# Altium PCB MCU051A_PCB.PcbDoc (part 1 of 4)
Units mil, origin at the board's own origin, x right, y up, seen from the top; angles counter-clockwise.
Board outline 4000 x 6000 mil, 6 copper layers (Top Layer, Signal Layer 1, Signal Layer 2, Signal Layer 3, Signal Layer 4, Bottom Layer), stack 60.4 mil thick; 193 components, 239 nets, 864 pads, 621 vias.
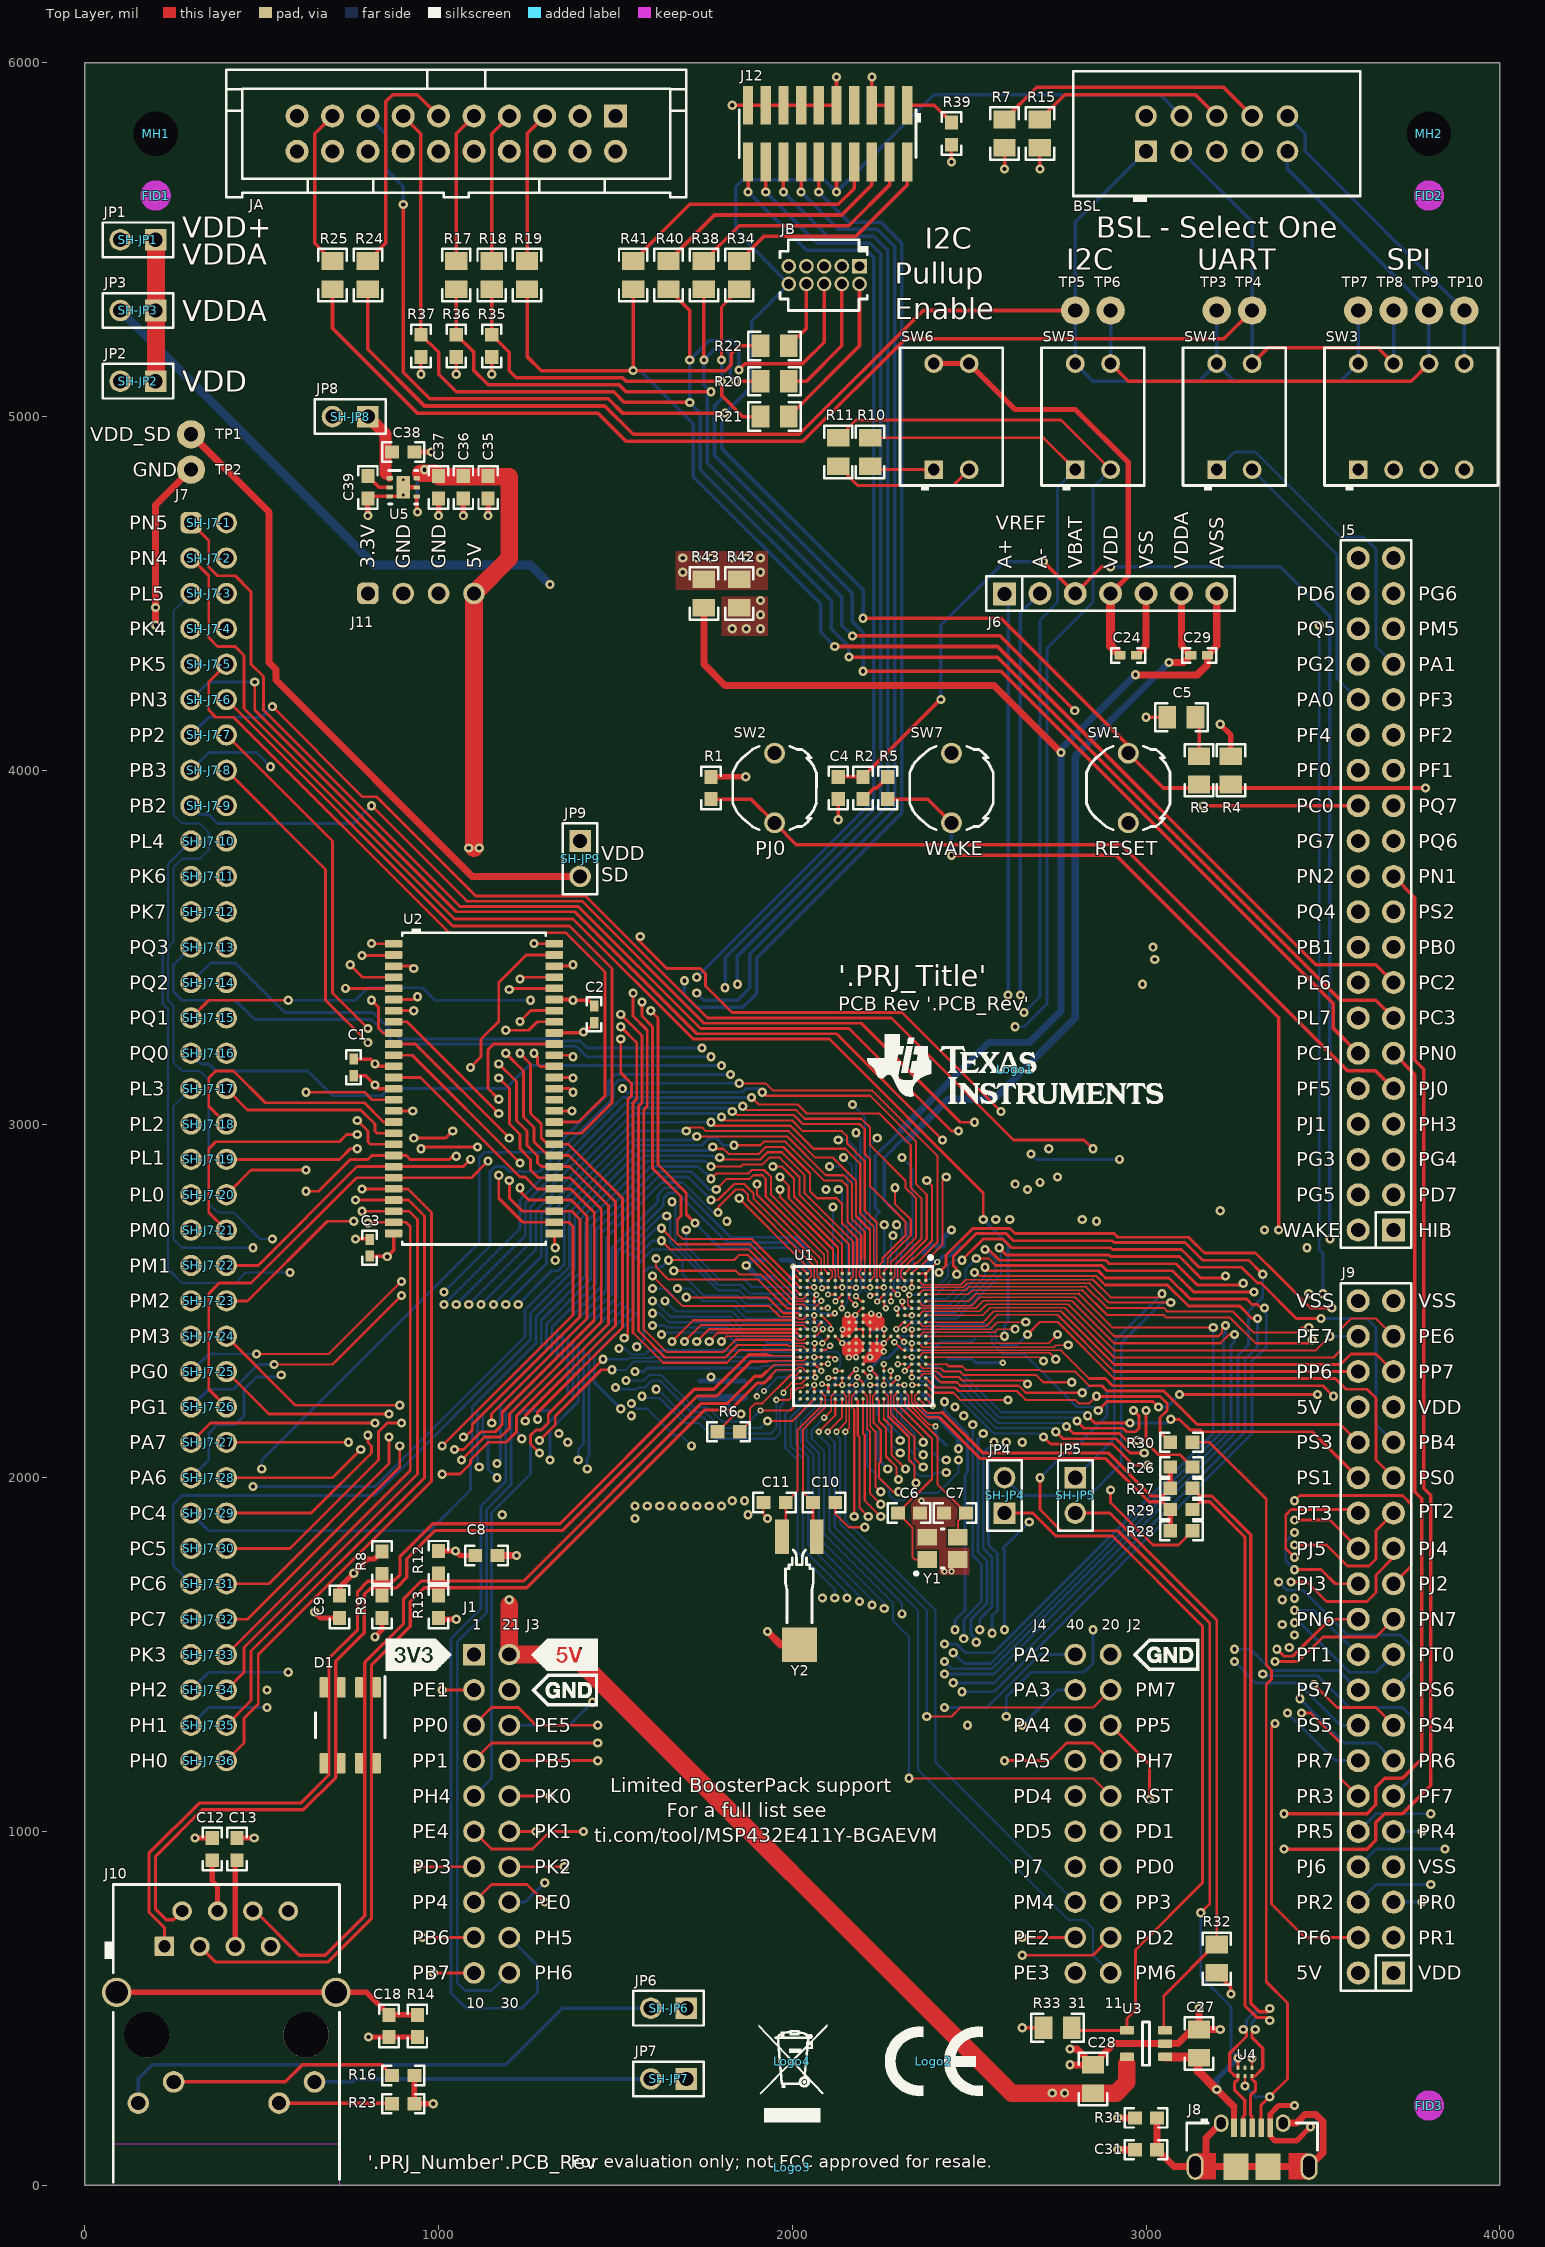
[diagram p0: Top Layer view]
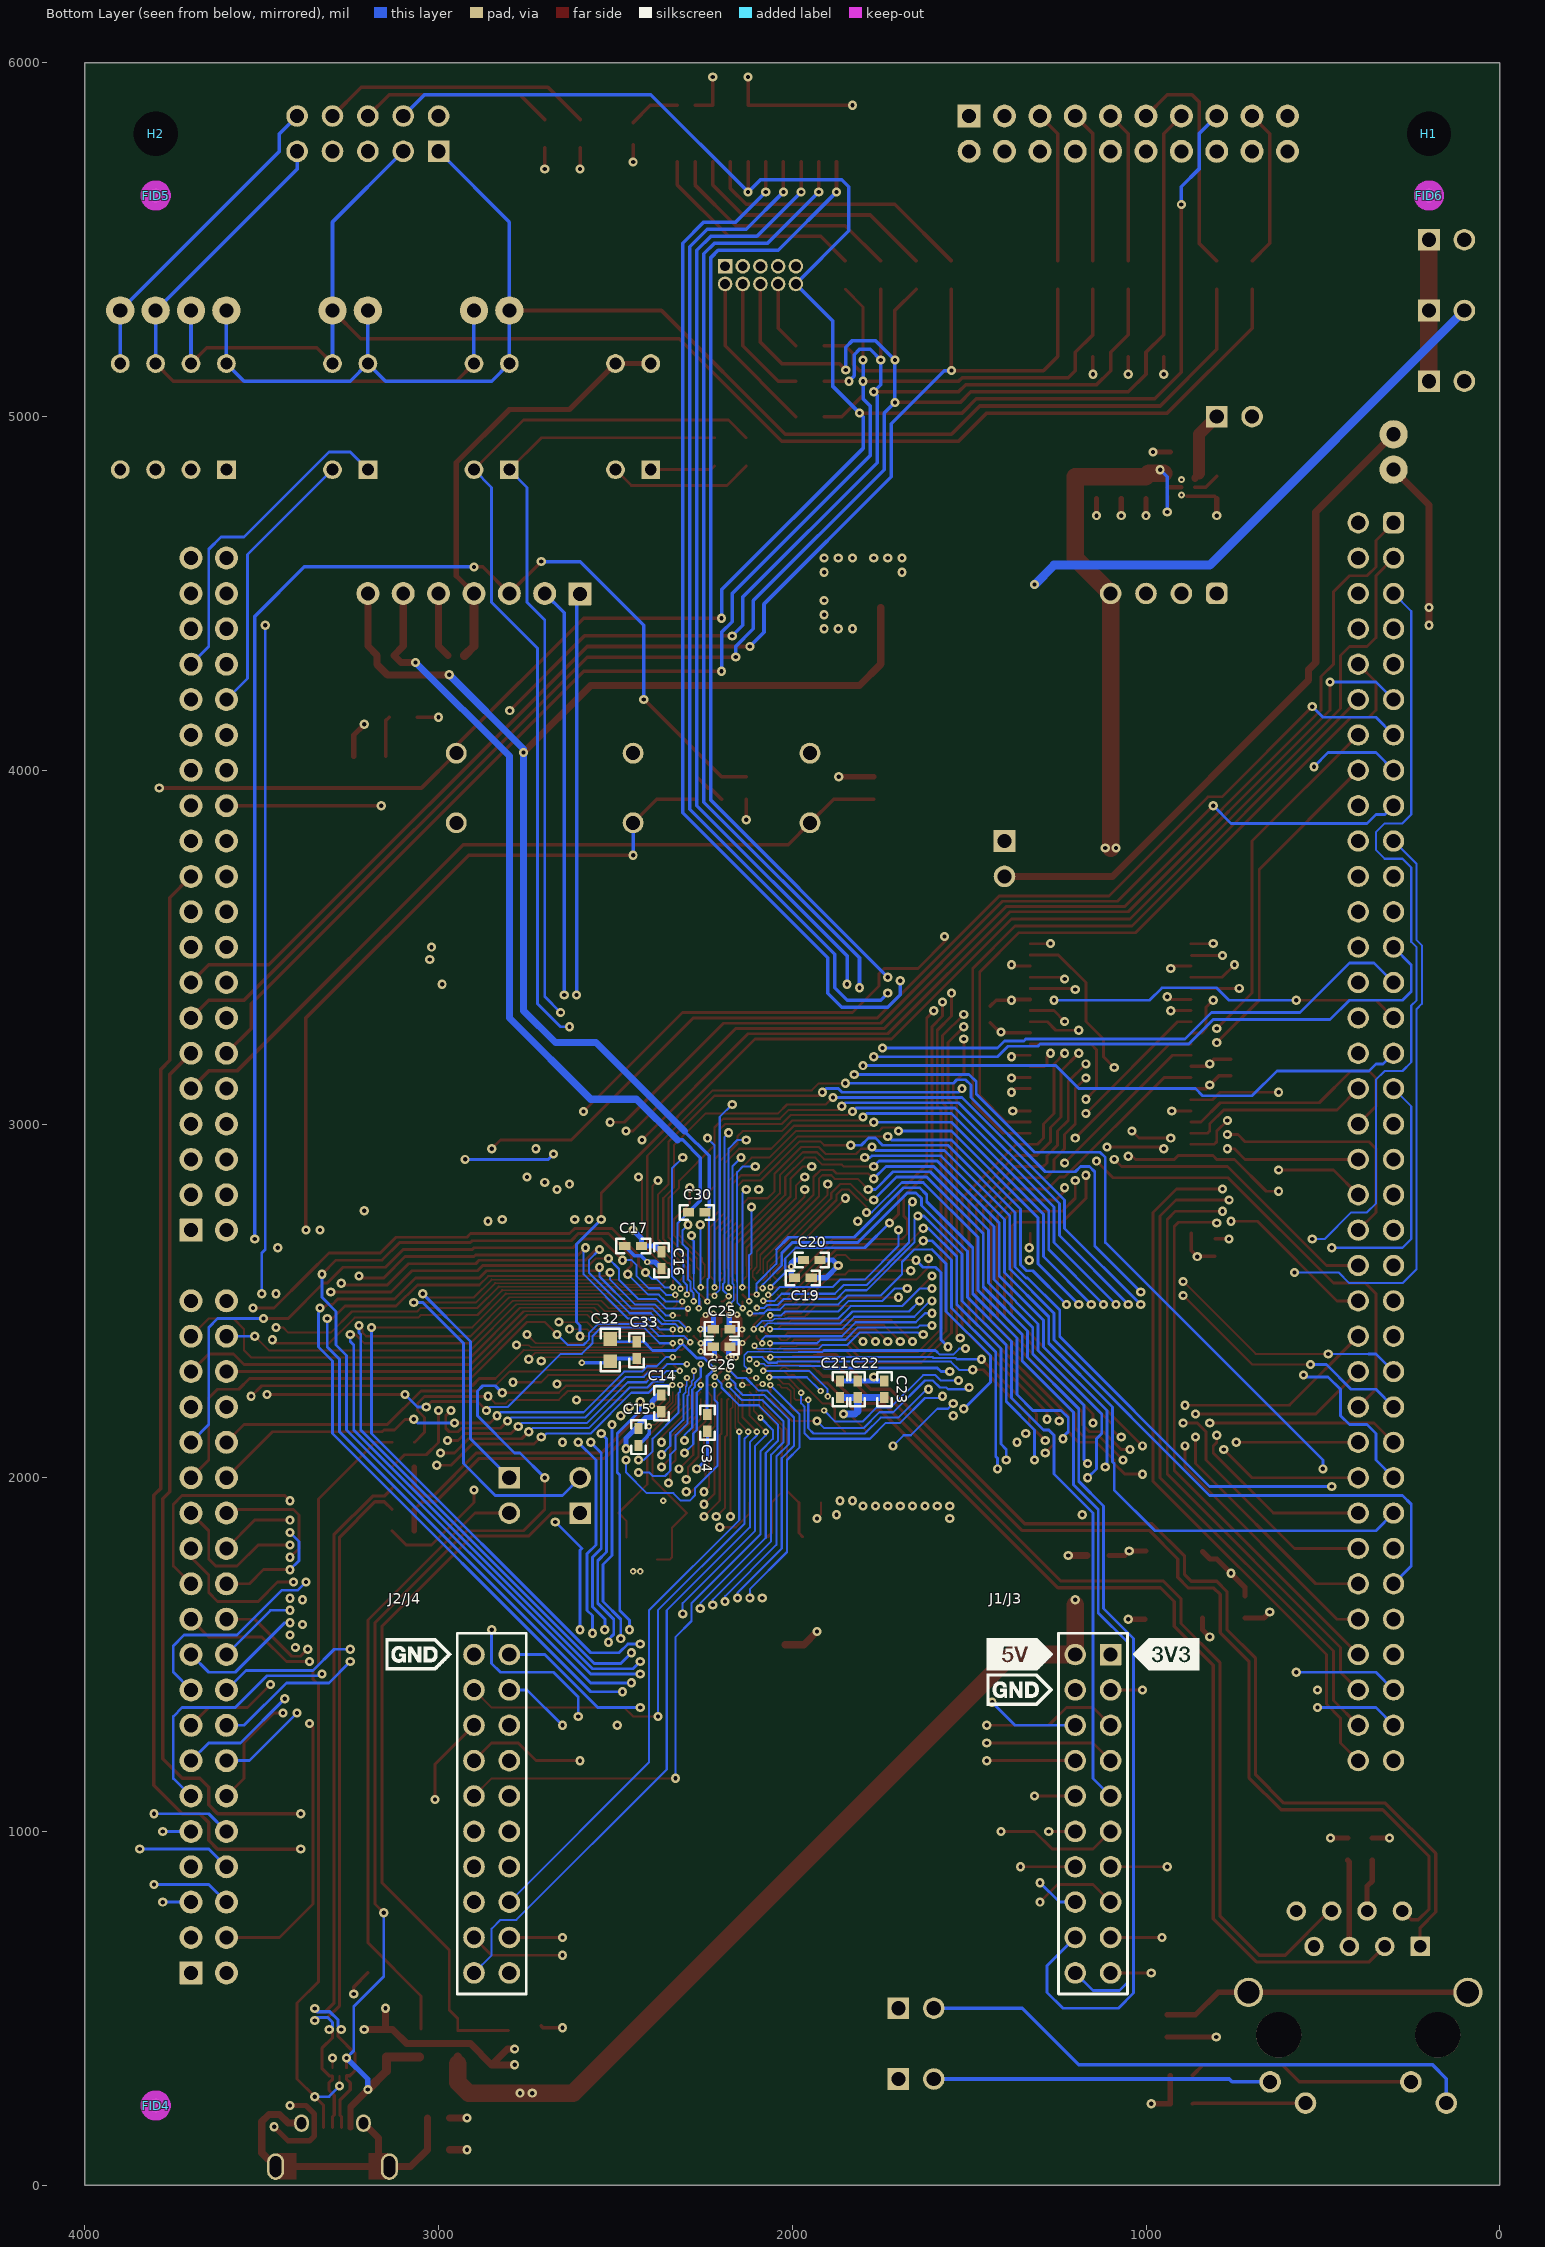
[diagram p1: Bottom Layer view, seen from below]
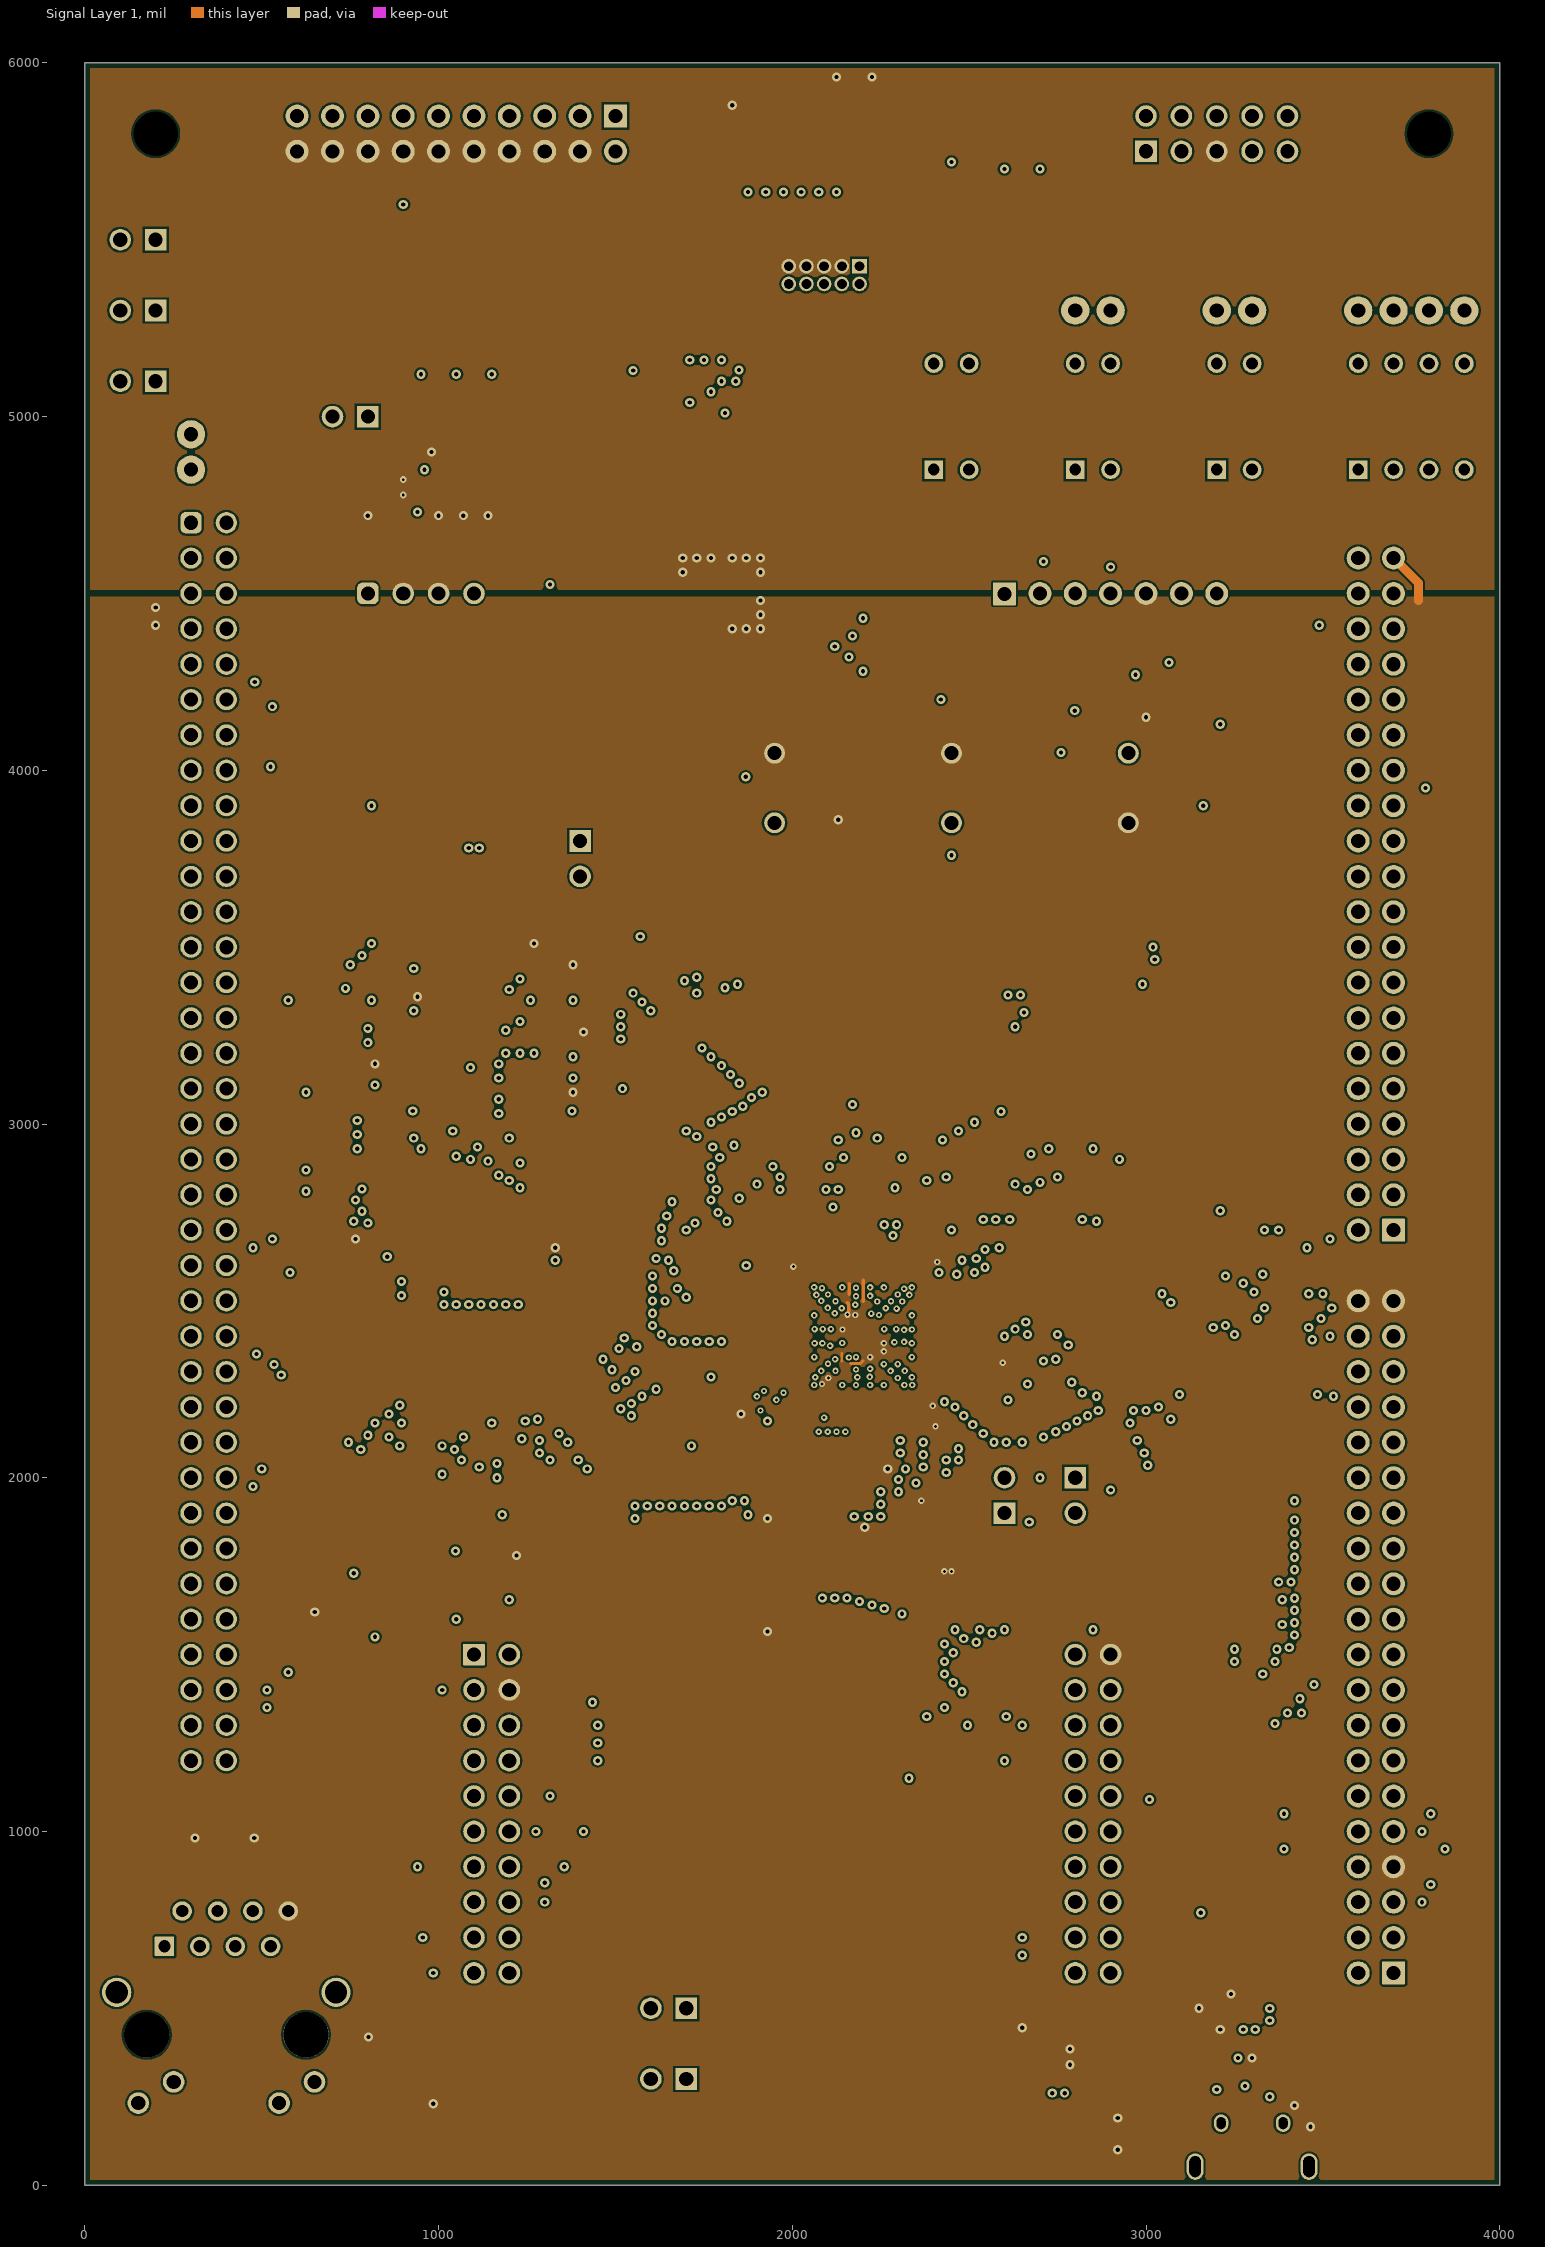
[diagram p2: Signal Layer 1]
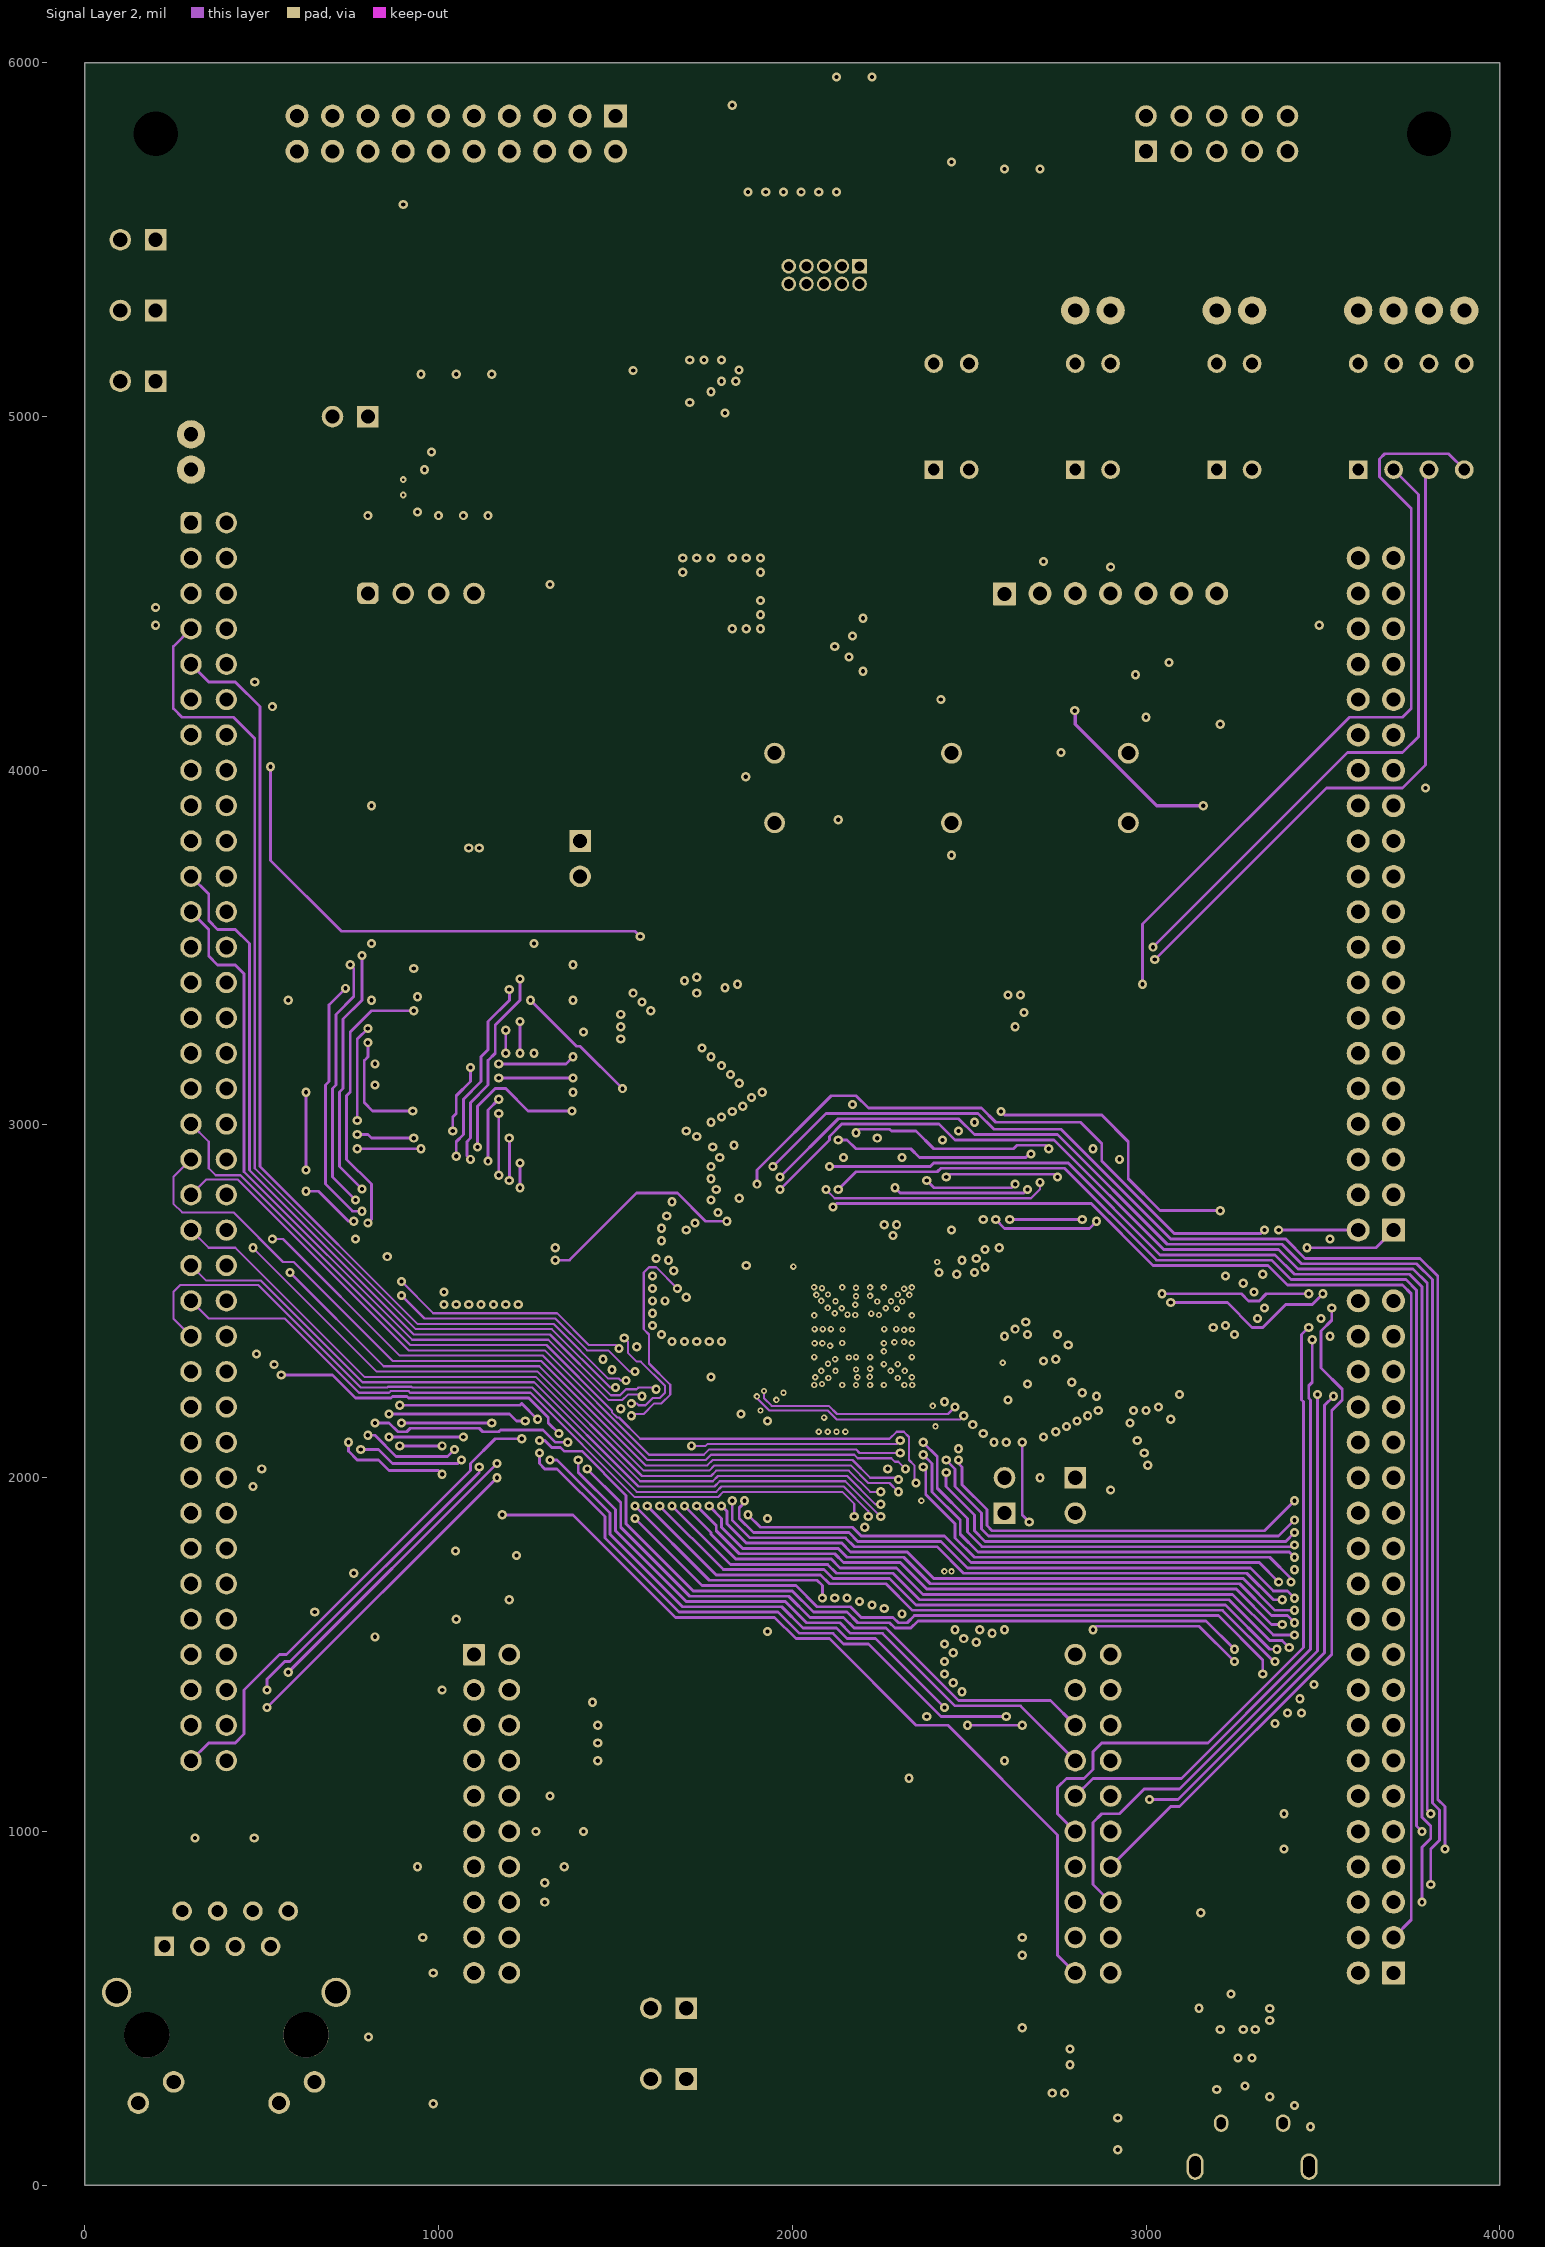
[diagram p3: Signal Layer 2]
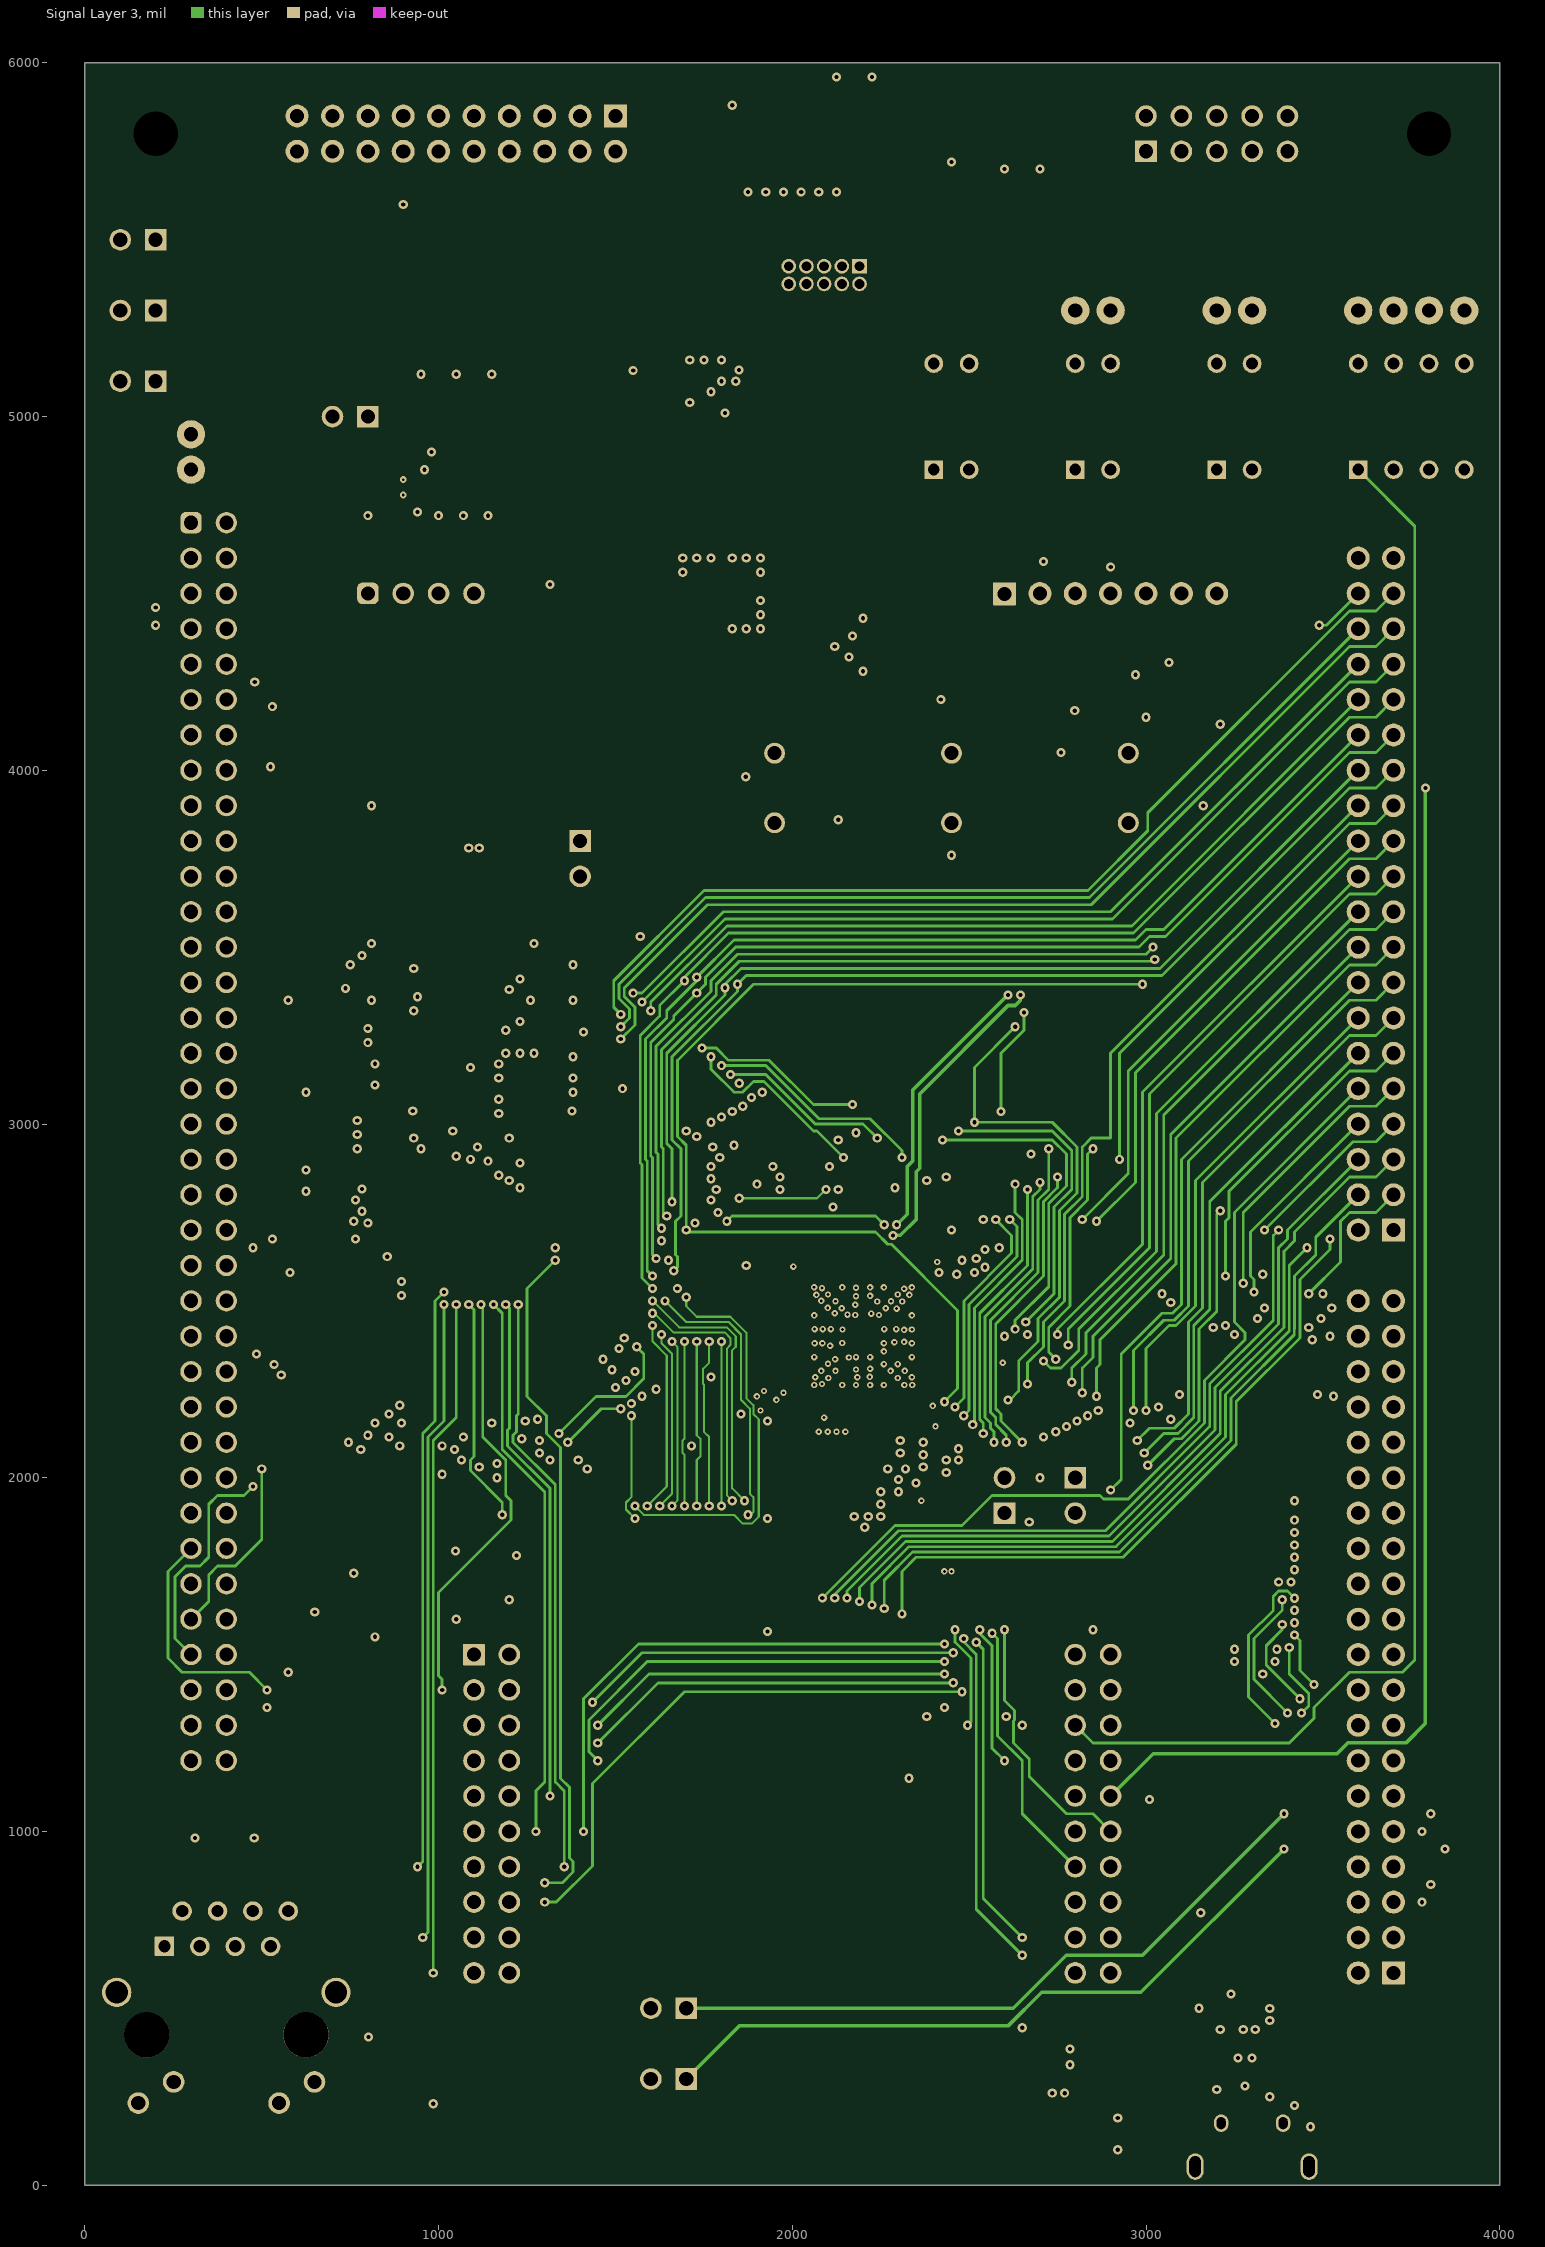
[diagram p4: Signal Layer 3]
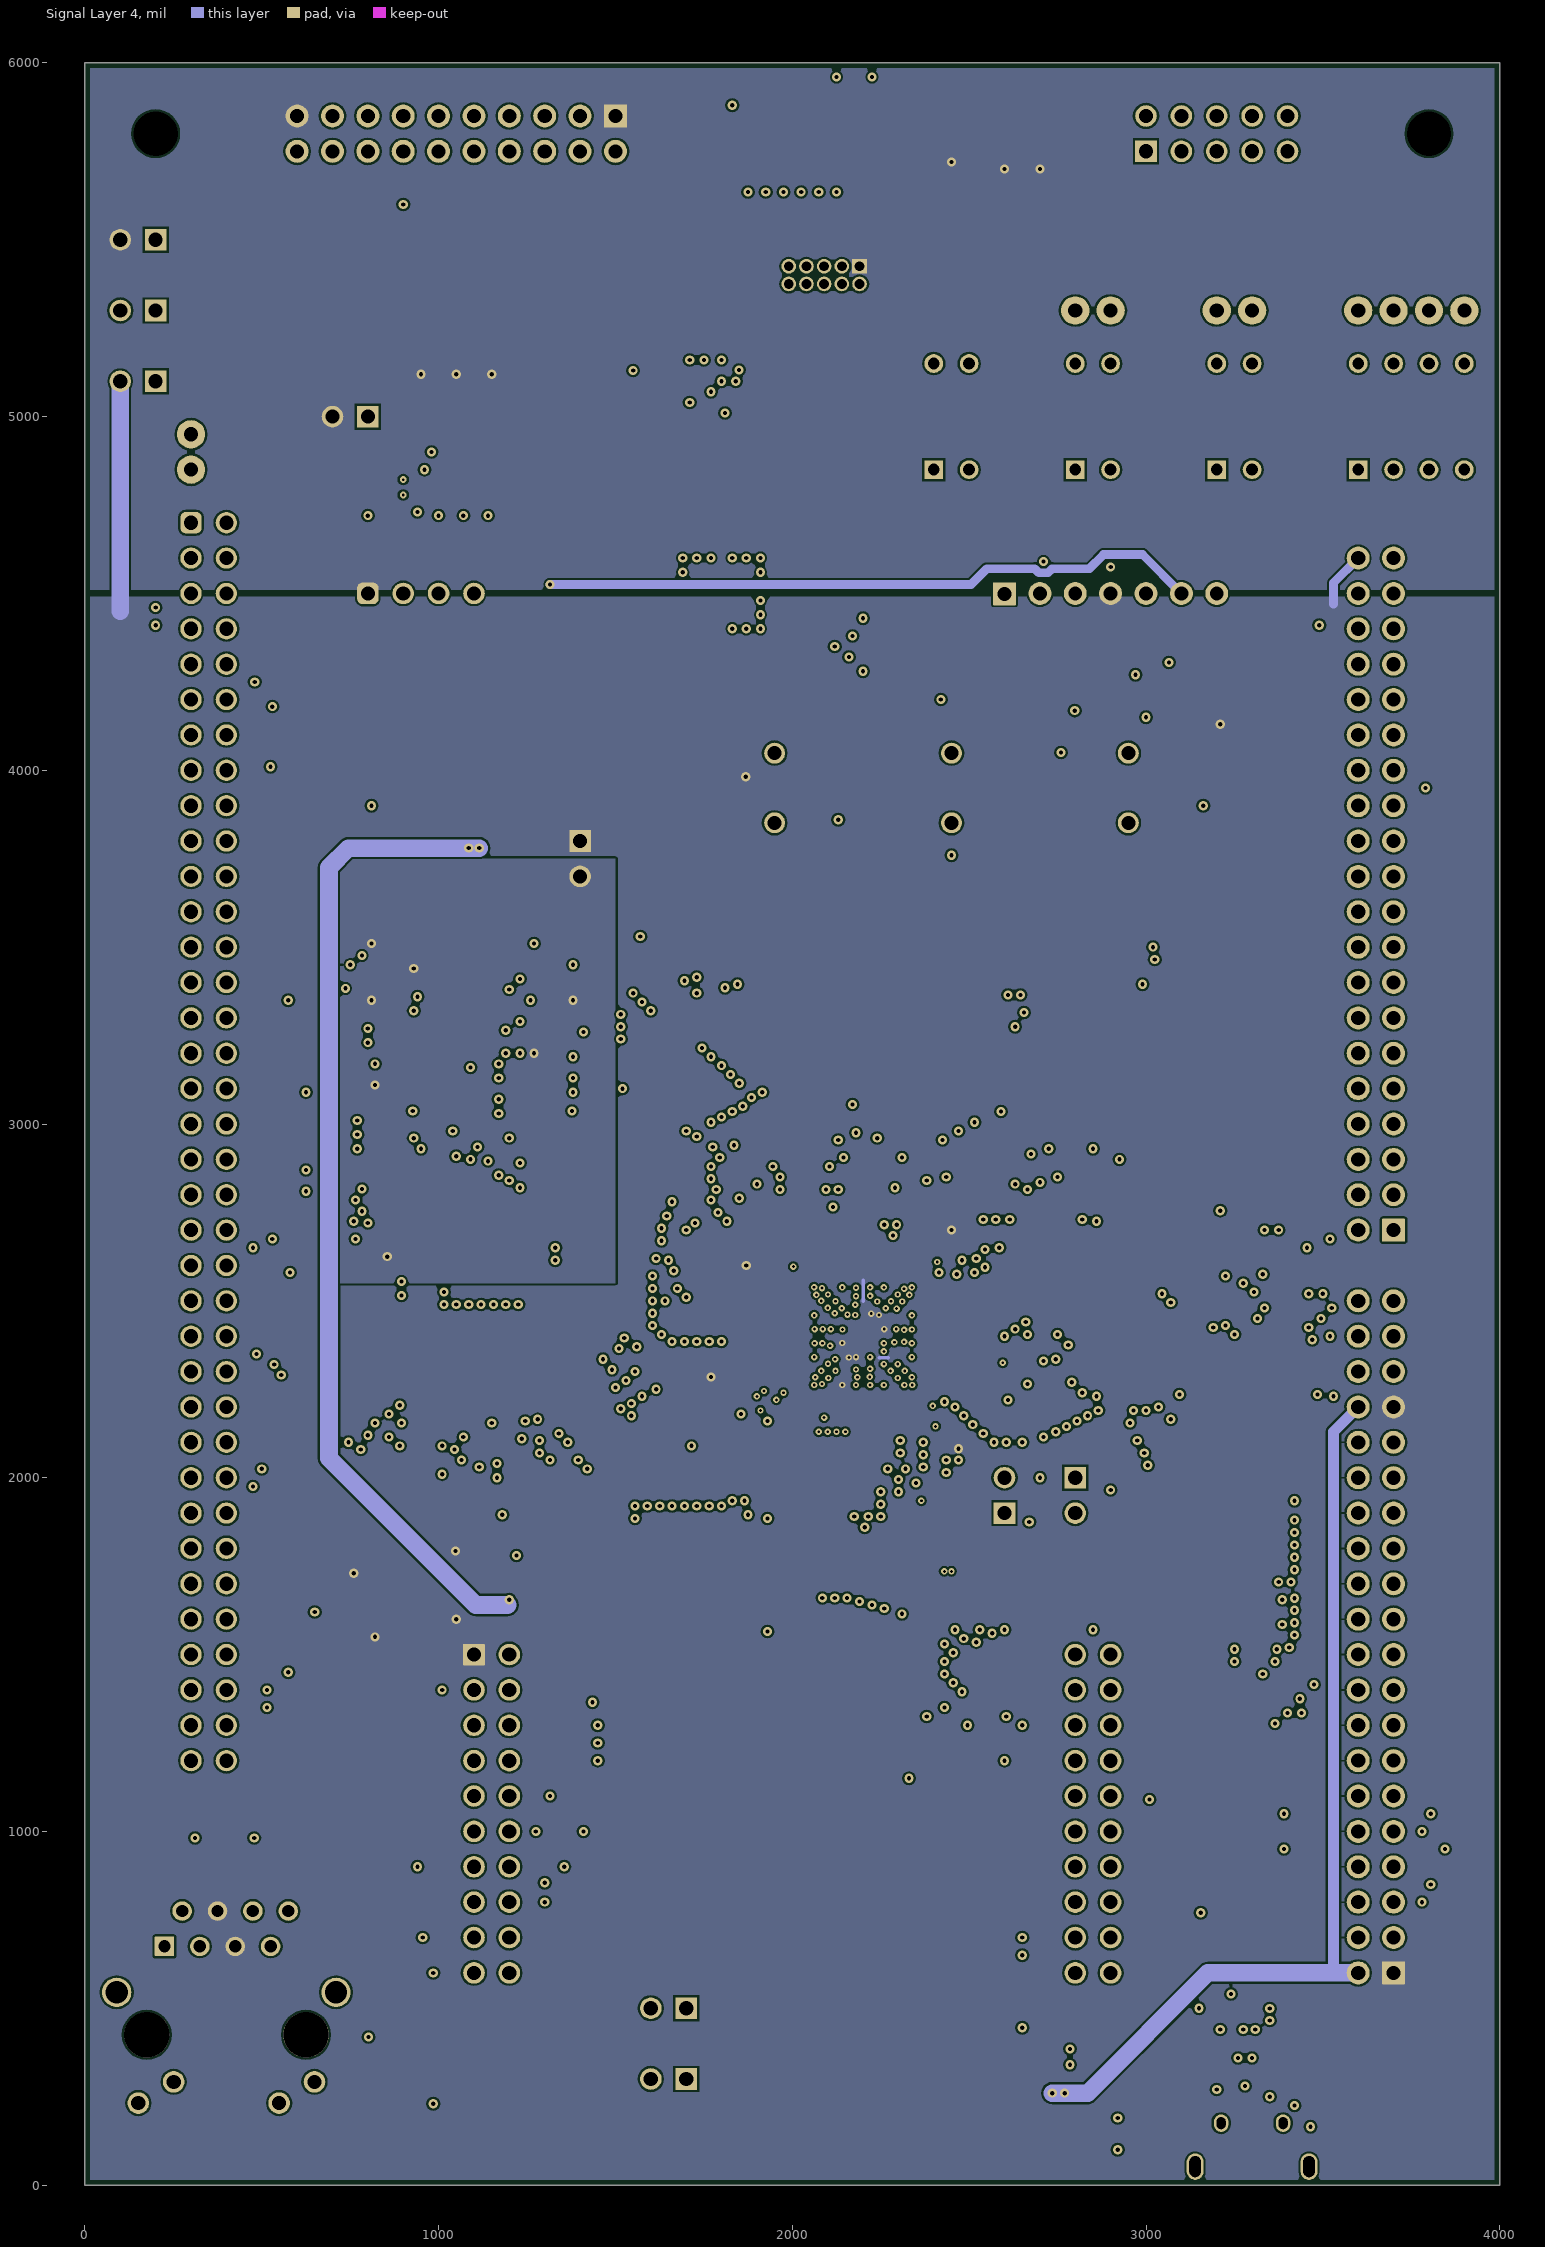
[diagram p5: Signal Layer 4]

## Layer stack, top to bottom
Top Solder: solder mask 0.8, Solder Resist, Dk 3.5
Top Layer: signal copper 1.9
Dielectric 1: prepreg 7.7, FR-4 or VT47, Dk 4.2
Signal Layer 1: signal copper 1.2
Dielectric 2: core 14, FR-4 or VT47, Dk 4.2
Signal Layer 2: signal copper 1.2
Dielectric 3: prepreg 8.4, FR-4 or VT47, Dk 4.2
Signal Layer 3: signal copper 1.2
Dielectric 4: core 14, FR-4 or VT47, Dk 4.2
Signal Layer 4: signal copper 1.2
Dielectric 5: prepreg 7.7, FR-4 or VT47, Dk 4.2
Bottom Layer: signal copper 1.9
Bottom Solder: solder mask 0.8, Solder Resist, Dk 3.5

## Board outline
0,0 0,6000 4000,6000 4000,0

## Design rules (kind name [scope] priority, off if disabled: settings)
AcuteAngle [All] p1: minimum=4.50000000000000E+0001 checktracksonly=FALSE
AssemblyTestPointUsage [All] p1: valid=2
BoardOutlineClearance BoardOutlineClearance_EthConn [InComponent('J10')] p1: gap=0 ignorepadtopadclearanceinfootprint=FALSE
BoardOutlineClearance BoardOutlineClearance_USBConn [InComponent('J8')] p2: gap=0 ignorepadtopadclearanceinfootprint=FALSE
BoardOutlineClearance BoardOutlineClearance_MountingHoles [OnCopper and InComponentClass('Mounting Holes')] p3: gap=40 ignorepadtopadclearanceinfootprint=FALSE
BoardOutlineClearance BoardOutlineClearance_Poly [OnCopper and IsPoly] p4: gap=15 ignorepadtopadclearanceinfootprint=FALSE
BoardOutlineClearance [OnCopper and Not InComponentClass('Logo') and not InComponentClass('FiducialMark') and not InRegion(1000,500,4000,800) and not InPoly] p5: gap=20 ignorepadtopadclearanceinfootprint=FALSE
Clearance Clearance_432E [TouchesRoom('MCU051A_Power_JTAG')] p1: gap=6 ignorepadtopadclearanceinfootprint=FALSE except(0: Arc-Hole Track-Hole SMDPad-Hole THPad-Hole Via-Hole Fill-Hole Poly-Hole Region-Hole Text-Hole; 4: Arc-Arc Arc-Track Arc-SMDPad Arc-Via Arc-Fill Arc-Poly Arc-Region Track-Track Track-SMDPad Track-Via Track-Fill Track-Poly Track-Region Via-Via; 5: SMDPad-Via; 7.87: Arc-Text Track-Text SMDPad-SMDPad SMDPad-THPad SMDPad-Text THPad-THPad THPad-Via THPad-Text Via-Text Fill-Text Poly-Text Region-Text Text-Text)
Clearance Clearance_Poly [InPolygon] p2: gap=6 ignorepadtopadclearanceinfootprint=FALSE
Clearance Clearance_Keepouts [((IsTrack Or IsArc) And Not InPoly) And IsFree and IsKeepOut vs ((IsTrack Or IsArc) And Not InPoly) And IsFree and IsKeepOut] p3: gap=0 ignorepadtopadclearanceinfootprint=FALSE
Clearance Clearance_FiducialMark [IsKeepOut and InComponentClass('FiducialMark') vs IsPad and InComponentClass('FiducialMark')] p4: gap=0 ignorepadtopadclearanceinfootprint=FALSE
Clearance [All] p5: gap=6 ignorepadtopadclearanceinfootprint=FALSE except(7.87: Arc-Text Track-Text SMDPad-THPad SMDPad-Text THPad-THPad THPad-Via THPad-Text Via-Text Fill-Text Poly-Text Region-Text Text-Text)
ComponentClearance ComponentClearance_TestPoint [HasFootprint('Keystone5001') vs HasFootprint('Keystone5001')] p1: gap=1.5 collisioncheckmode=3 verticalgap=10 showdistances=FALSE
ComponentClearance ComponentClearance_MountingHoles_FiducialMarks [HasFootprint('Keystone_1902B') vs InComponentClass('FiducialMark')] p2: gap=5 collisioncheckmode=3 verticalgap=10 showdistances=FALSE
ComponentClearance ComponentClearance_Shunt [InComponentClass('Header') vs InComponentClass('Shunt')] p3: gap=0 collisioncheckmode=3 verticalgap=0 showdistances=FALSE
ComponentClearance ComponentClearance_ShuntToShunt [InComponentClass('Shunt') vs InComponentClass('Shunt')] p4: gap=0 collisioncheckmode=3 verticalgap=0 showdistances=FALSE
ComponentClearance ComponentClearance_Logo [InComponentClass('Logo')] p5: gap=50 collisioncheckmode=3 verticalgap=10 showdistances=FALSE
ComponentClearance ComponentClearance_ScrewToNut [(HasFootprint('NY PMS 440 0025 PH')) vs (HasFootprint('Keystone_1902C'))] p6: gap=5 collisioncheckmode=3 verticalgap=10 showdistances=FALSE
ComponentClearance ComponentClearance_MountingHoles [InComponentClass('Mounting Holes')] p7: gap=10 collisioncheckmode=3 verticalgap=100000 showdistances=FALSE
ComponentClearance ComponentClearance_SmallPassives [HasFootprint('0201*') or HasFootprint('0402*') or HasFootprint('0508') or HasFootprint('0603*') or HasFootprint('0612') or HasFootprint('0805*') or HasFootprint('0815*') or HasFootprint('0830*') or HasFootprint('1206*') or HasFootprint('1210*') or HasFootprint('1808*') or HasFootprint('1812*') or HasFootprint('1825*') or HasFootprint('2010*') or HasFootprint('2220*') or HasFootprint('2225*') or HasFootprint('2512*') or HasFootprint('2728*') or HasFootprint('3518*') vs HasFootprint('0201*') or HasFootprint('0402*') or HasFootprint('0508') or HasFootprint('0603*') or HasFootprint('0612') or HasFootprint('0805*') or HasFootprint('0815*') or HasFootprint('0830*') or HasFootprint('1206*') or HasFootprint('1210*') or HasFootprint('1808*') or HasFootprint('1812*') or HasFootprint('1825*') or HasFootprint('2010*') or HasFootprint('2220*') or HasFootprint('2225*') or HasFootprint('2512*') or HasFootprint('2728*') or HasFootprint('3518*')] p8: gap=10 collisioncheckmode=3 verticalgap=10 showdistances=FALSE
ComponentClearance ComponentClearance_THtoSMT [IsThruComponent vs IsSMTComponent] p9: gap=20 collisioncheckmode=3 verticalgap=30 showdistances=FALSE
ComponentClearance ComponentClearance_THtoTH [IsThruComponent vs IsThruComponent] p10: gap=10 collisioncheckmode=3 verticalgap=30 showdistances=FALSE
ComponentClearance [All] p11: gap=30 collisioncheckmode=3 verticalgap=10 showdistances=FALSE
DiffPairsRouting DiffPairsRouting_USB [InDifferentialPair('D') Or InDifferentialPair('OTGD')] p1: maxlimit=10 minlimit=4 mostfreqgap=7 toplayer_minwidth=4 toplayer_maxwidth=15 toplayer_prefwidth=9 midlayer1_minwidth=4 midlayer1_maxwidth=15 midlayer1_prefwidth=9 midlayer2_minwidth=4 midlayer2_maxwidth=15 midlayer2_prefwidth=9 midlayer3_minwidth=4 midlayer3_maxwidth=15 midlayer3_prefwidth=9 midlayer4_minwidth=4 midlayer4_maxwidth=15 midlayer4_prefwidth=9 bottomlayer_minwidth=4 bottomlayer_maxwidth=15 bottomlayer_prefwidth=9 maxuncoupledlength=500
DiffPairsRouting DiffPairsRouting_Ethernet [InDifferentialPair('EN0RXI') Or InDifferentialPair('EN0TXO')] p2: maxlimit=15 minlimit=4 mostfreqgap=10 toplayer_minwidth=4 toplayer_maxwidth=15 toplayer_prefwidth=9 midlayer1_minwidth=4 midlayer1_maxwidth=15 midlayer1_prefwidth=9 midlayer2_minwidth=4 midlayer2_maxwidth=15 midlayer2_prefwidth=9 midlayer3_minwidth=4 midlayer3_maxwidth=15 midlayer3_prefwidth=9 midlayer4_minwidth=4 midlayer4_maxwidth=15 midlayer4_prefwidth=9 bottomlayer_minwidth=4 bottomlayer_maxwidth=15 bottomlayer_prefwidth=9 maxuncoupledlength=500
DiffPairsRouting [All] p3: maxlimit=100 minlimit=10 mostfreqgap=10 toplayer_minwidth=15 toplayer_maxwidth=15 toplayer_prefwidth=15 midlayer1_minwidth=15 midlayer1_maxwidth=15 midlayer1_prefwidth=15 midlayer2_minwidth=15 midlayer2_maxwidth=15 midlayer2_prefwidth=15 midlayer3_minwidth=15 midlayer3_maxwidth=15 midlayer3_prefwidth=15 midlayer4_minwidth=15 midlayer4_maxwidth=15 midlayer4_prefwidth=15 bottomlayer_minwidth=15 bottomlayer_maxwidth=15 bottomlayer_prefwidth=15 maxuncoupledlength=1000
FabricationTestPointUsage TestPointUsage [All] p1: valid=2 allowmultiple=FALSE
FabricationTestpoint Testpoint [All] p1: side=3 testpointundercomponent=TRUE minsize=40 maxsize=100 preferedsize=60 minholesize=0 maxholesize=40 preferedholesize=32 testpointgrid=1 allowsidetop=TRUE allowsidebottom=TRUE usegrid=TRUE gridtolerance=0.01
FanoutControl Fanout_LCC [IsLCC] p1: bgadir=Out bgaviamode=Centered fanoutstyle=Auto fanoutdirection=Alternating viagrid=1 // Fanout_LCC (Default Rule)
FanoutControl Fanout_BGA [IsBGA] p2: bgadir=Out bgaviamode=Centered fanoutstyle=Auto fanoutdirection=Alternating viagrid=1 // Fanout_BGA (Default Rule)
FanoutControl Fanout_Default [All] p4: bgadir=Out bgaviamode=Centered fanoutstyle=Auto fanoutdirection=Alternating viagrid=1 // Fanout_Default (Default Rule)
FanoutControl Fanout_Small [(CompPinCount < 5)] p5: bgadir=Out bgaviamode=Centered fanoutstyle=Auto fanoutdirection=OutThenIn viagrid=1 // Fanout_Small (Default Rule)
HoleSize [All] p1: absolutevalues=TRUE maxlimit=251 minlimit=7.87 maxpercent=80.000 minpercent=20.000
MinimumAnnularRing MinimumAnnularRing_via [IsVia] p1: minimumring=5
MinimumAnnularRing MinimumAnnularRing_ThermalPadVias [IsVia and InAnyComponent] p2: minimumring=5.91
MinimumAnnularRing [All] p3: minimumring=6.6
MinimumSolderMaskSliver MinimumSolderMaskSliver_Logo [InComponentClass('Logo') vs InComponentClass('Logo')] p1: minsoldermaskwidth=0.7
MinimumSolderMaskSliver [All] p2: minsoldermaskwidth=3.94
PlaneConnect [All] p1: planeconnectstyle=Relief reliefexpansion=10 reliefentries=4 reliefconductorwidth=10 reliefairgap=10
PolygonConnect [All] p1: connectstyle=Direct reliefconductorwidth=10 reliefentries=4 polygonreliefangle="90 Angle" airgapwidth=10
RoomDefinition MCU051A_Power_JTAG [InComponentClass('MCU051A_Power_JTAG')] p1 off: confinementstyle=ConfineIn formatcopy=TRUE lockcomponents=FALSE outline 1595,2965 2695,2965 2695,1865 1595,1865
RoutingVias ThermalPadVias [IsVia and InAnyComponent] p1: holewidth=7.87 width=19.68 viastyle="Through Hole" minholewidth=7.87 minwidth=19.68 maxholewidth=12.99 maxwidth=23.62
RoutingVias [All] p2: holewidth=12 width=28 viastyle="Through Hole" minholewidth=7.87 minwidth=18 maxholewidth=40 maxwidth=65
SilkToBoardRegionClearance [Not ((IsComment or IsDesignator) And (Hide <> 'False')) and not InRegion(1000,500,4000,800)] p1:
SilkToSilkClearance SilkToSilkClearance_Pb-FreeLogo [(HasFootprint('Pb-Free_Overlay_Medium') OR HasFootprint('Pb-Free_Overlay_Small')) vs (HasFootprint('Pb-Free_Overlay_Medium') OR HasFootprint('Pb-Free_Overlay_Small'))] p1: silktosilkclearance=0
SilkToSilkClearance [All] p2: silktosilkclearance=4
SilkToSolderMaskClearance SilkToComponentPadClearance [(IsPad or IsFill or IsRegion) and InAnycomponent] p1: minsilkscreentomaskgap=5 clearancetoexposedcopper=TRUE
SilkToSolderMaskClearance "Silk to Solder Mask Opening" [All] p2: minsilkscreentomaskgap=4 clearancetoexposedcopper=FALSE
SolderMaskExpansion [All] p1: expansion=1.97
Width [All] p1: maxlimit=100 minlimit=4 preferedwidth=10 midlayer1_minwidth=6 midlayer2_minwidth=6 midlayer3_minwidth=6 midlayer4_minwidth=6 minimp=50.000000 maximp=50.000000 favimp=50.000000 checkconnectedcopper=TRUE
15 further rules are at their usual default settings.

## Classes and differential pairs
component class Shunt: SH-J7-1 SH-J7-2 SH-J7-3 SH-J7-4 SH-J7-5 SH-J7-6 SH-J7-7 SH-J7-8 SH-J7-9 SH-J7-10 SH-J7-11 SH-J7-12 SH-J7-13 SH-J7-14 SH-J7-15 SH-J7-16 SH-J7-17 SH-J7-18 SH-J7-19 SH-J7-20 SH-J7-21 SH-J7-22 SH-J7-23 SH-J7-24 SH-J7-25 SH-J7-26 SH-J7-27 SH-J7-28 SH-J7-29 SH-J7-30 SH-J7-31 SH-J7-32 SH-J7-33 SH-J7-34 SH-J7-35 SH-J7-36 SH-JP1 SH-JP2 SH-JP3 SH-JP4 SH-JP5 SH-JP6 SH-JP7 SH-JP8 SH-JP9
component class MCU051A_Power_JTAG: BSL C35 C36 C37 C38 C39 J11 J12 JA JB JP1 JP2 JP3 JP8 R7 R10 R11 R15 R17 R18 R19 R20 R21 R22 R24 R25 R34 R35 R36 R37 R38 R39 R40 R41 R42 R43 SW3 SW4 SW5 SW6 TP3 TP4 TP5 TP6 TP7 TP8 TP9 TP10 U5
component class MCU051A_MSP432E_Device: C4 C5 C6 C7 C8 C9 C10 C11 C12 C13 C14 C15 C16 C17 C18 C19 C20 C21 C22 C23 C24 C25 C26 C27 C28 C29 C30 C31 C32 C33 C34 D1 J5 J6 J8 J10 JP4 JP5 JP6 JP7 R1 R2 R3 R4 R5 R6 R8 R9 R12 R13 R14 R16 R23 R26 R27 R28 R29 R30 R31 R32 R33 SW1 SW2 SW7 U1 U3 U4 Y1 Y2
component class MCU051A_LCD_Memory: C1 C2 C3 J1/J3 J2/J4 J7 J9 J19 JP9 TP1 TP2 U2
component class Header: J5 J6 J7 J9 J11 J19 JP1 JP2 JP3 JP4 JP5 JP6 JP7 JP8 JP9
component class Logo: Logo1
component class MCU051A_EVM_Hardware: FID1 FID2 FID3 FID4 FID5 FID6 H1 H2 Logo1 Logo2 Logo3 Logo4 MH1 MH2 SH-J7-1 SH-J7-2 SH-J7-3 SH-J7-4 SH-J7-5 SH-J7-6 SH-J7-7 SH-J7-8 SH-J7-9 SH-J7-10 SH-J7-11 SH-J7-12 SH-J7-13 SH-J7-14 SH-J7-15 SH-J7-16 SH-J7-17 SH-J7-18 SH-J7-19 SH-J7-20 SH-J7-21 SH-J7-22 SH-J7-23 SH-J7-24 SH-J7-25 SH-J7-26 SH-J7-27 SH-J7-28 SH-J7-29 SH-J7-30 SH-J7-31 SH-J7-32 SH-J7-33 SH-J7-34 SH-J7-35 SH-J7-36 SH-JP1 SH-JP2 SH-JP3 SH-JP4 SH-JP5 SH-JP6 SH-JP7 SH-JP8 SH-JP9 ZZ2 ZZ3 ZZ4 ZZ5 ZZ6
component class FiducialMark: FID1 FID2 FID3 FID4 FID5 FID6
component class AssemblyNote: ZZ2 ZZ3 ZZ4 ZZ5 ZZ6
differential pair OTGD: +OTGD_P -OTGD_N
differential pair EN0TXO: +EN0TXO_P -EN0TXO_N
differential pair EN0RXI: +EN0RXI_P -EN0RXI_N
differential pair D: +D_P -D_N

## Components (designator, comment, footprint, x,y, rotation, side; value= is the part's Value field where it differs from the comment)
BSL "AWHW-10G-0202-T" Assman_AWHW-10G-0x02-T 3200,5800 r90 top
C1 "GRM155R71A104KA01D" 0402 760,3160 r270 top value=0.1uF
C2 "GRM155R71A104KA01D" 0402 1440,3310 r90 top value=0.1uF
C3 "GRM155R71A104KA01D" 0402 805,2650 r270 top value=0.1uF
C4 "GRM188R71C104KA01D" 0603 2130,3950 r270 top value=0.1uF
C5 "C0805C104K4RACTU" 0805_HV 3100,4150 r0 top value=0.1uF
C6 "GRM1885C1H120JA01D" 0603 2330,1900 r180 top value=12pF
C7 "GRM1885C1H120JA01D" 0603 2460,1900 r0 top value=12pF
C8 "GRM188R71C104KA01D" 0603 1135,1780 r0 top value=0.1uF
C9 "GRM188R71C104KA01D" 0603 720,1635 r270 top value=0.1uF
C10 "GRM1885C1H120JA01D" 0603 2090,1930 r180 top value=12pF
C11 "GRM1885C1H120JA01D" 0603 1950,1930 r0 top value=12pF
C12 "GRM188R71C104KA01D" 0603 360,950 r90 top value=0.1uF
C13 "GRM188R71C104KA01D" 0603 430,950 r90 top value=0.1uF
C14 "GRM155R71A104KA01D" 0402 2370.32,2210 r270 bottom value=0.1uF
C15 "GRM155R71A104KA01D" 0402 2435,2115 r90 bottom value=0.1uF
C16 "GRM155R71A104KA01D" 0402 2370,2615 r90 bottom value=0.1uF
C17 "GRM155R71A104KA01D" 0402 2450,2655 r180 bottom value=0.1uF
C18 "06031C472KAT2A" 0603 860,450 r270 top value=4700pF
C19 "GRM155R71A104KA01D" 0402 1970,2565 r180 bottom value=0.1uF
C20 "GRM155R71A104KA01D" 0402 1945,2615.63 r180 bottom value=0.1uF
C21 "GRM155R71A104KA01D" 0402 1865,2250 r90 bottom value=0.1uF
C22 "GRM155R71A104KA01D" 0402 1815,2250 r90 bottom value=0.1uF
C23 "GRM155R71A104KA01D" 0402 1740,2250 r90 bottom value=0.1uF
C24 "GRM155R71A104KA01D" 0402 2950,4325 r180 top value=0.1uF
C25 "GRM155R71A104KA01D" 0402 2200,2419.69 r0 bottom value=0.1uF
C26 "GRM155R71A104KA01D" 0402 2200,2370 r180 bottom value=0.1uF
C27 "885012207025" 0805_HV 3150,400 r90 top value=4.7uF
C28 "885012207025" 0805_HV 2850,300 r90 top value=4.7uF
C29 "GRM155R70J105KA12D" 0402 3150,4325 r180 top value=1uF
C30 "GRM155R71A104KA01D" 0402 2270,2750 r0 bottom value=0.1uF
C31 "GRM188R71H224KAC4D" 0603 3000,100 r180 top value=0.22uF
C32 "GRM188Z71C225KE43" 0603 2515,2360.63 r270 bottom value=2.2uF
C33 "GRM155R70J105KA12D" 0402 2440,2360.63 r90 bottom value=1uF
C34 "GRM155R71A104KA01D" 0402 2240,2155 r90 bottom value=0.1uF
C35 "GRM188R71A105KA61D" 0603 1140,4800 r270 top value=1uF
C36 "GRM188R71C104KA01D" 0603 1070,4800 r270 top value=0.1uF
C37 "GRM188R71C103KA01D" 0603 1000,4800 r270 top value=0.01uF
C38 "GRM188Z71C225KE43" 0603 900,4900 r0 top value=2.2uF
C39 "GRM188R71C103KA01D" 0603 800,4800 r270 top value=0.01uF
D1 "CDNBS08-SLVU2.8-4" SOIC-8 750,1300 r270 top
FID1 "Fiducial" Fiducial10-20 200,5625 r0 top
FID2 "Fiducial" Fiducial10-20 3800,5625 r0 top
FID3 "Fiducial" Fiducial10-20 3800,225 r0 top
FID4 "Fiducial" Fiducial10-20 3800,225 r180 bottom
FID5 "Fiducial" Fiducial10-20 3800,5625 r180 bottom
FID6 "Fiducial" Fiducial10-20 200,5625 r180 bottom
H1 "1902B" Keystone_1902B 200,5800 r180 bottom
H2 "1902B" Keystone_1902B 3800,5800 r180 bottom
J1/J3 "SSQ-110-03-T-D" BoosterPack_40pin_J1J3 1150,1050 r180 bottom
J2/J4 "SSQ-110-03-T-D" BoosterPack_40pin_J2J4 2850,1050 r180 bottom
J5 "TSW-120-07-G-D" TSW-120-07-G-D 3650,3650 r90 top
J6 "TSW-107-07-G-S" TSW-107-XX-XXX-S 2900,4500 r0 top
J7 "TSW-136-07-G-D" Samtec_TSW-136-07-x-D 350,2950 r0 top
J8 "ZX62D-AB-5P8(30)" Hirose-ZX62D-AB-5P8 3300,0 r0 top
J9 "TSW-120-07-G-D" TSW-120-07-G-D 3650,1550 r90 top
J10 "J0011D21BNL" Pulse_J0011D21BNL 400,0 r0 top
J11 "TSW-104-07-T-S" Samtec_TSW-104-07-T-S 950,4500 r0 top
J12 "FTSH-110-01-L-DV-K" Samtec_FTSH-110-01-x-DV-K 2100,5800 r270 top
JA "5103309-5" CONN_5103309-5 1050,5800 r180 top
JB "FTSH-105-01-F-D-K" Samtec_FTSH-105-01-x-D-K 2090,5400 r270 top
JP1 "HMTSW-102-07-G-S-240" SAMTEC_HMTSW-102-07-G-S-240 150,5500 r180 top
JP2 "HMTSW-102-07-G-S-240" SAMTEC_HMTSW-102-07-G-S-240 150,5100 r180 top
JP3 "HMTSW-102-07-G-S-240" SAMTEC_HMTSW-102-07-G-S-240 150,5300 r180 top
JP4 "HMTSW-102-07-G-S-240" SAMTEC_HMTSW-102-07-G-S-240 2600,1950 r90 top
JP5 "HMTSW-102-07-G-S-240" SAMTEC_HMTSW-102-07-G-S-240 2800,1950 r270 top
JP6 "HMTSW-102-07-G-S-240" SAMTEC_HMTSW-102-07-G-S-240 1650,500 r180 top
JP7 "HMTSW-102-07-G-S-240" SAMTEC_HMTSW-102-07-G-S-240 1650,300 r180 top
JP8 "HMTSW-102-07-G-S-240" SAMTEC_HMTSW-102-07-G-S-240 750,5000 r180 top
JP9 "HMTSW-102-07-G-S-240" SAMTEC_HMTSW-102-07-G-S-240 1400,3750 r270 top
Logo1 "Texas Instruments" TI_Stacked_Overlay_Small 2630,3155 r0 top
Logo2 "CE Mark" CE_Mark_5mm 2400,350 r0 top
Logo3 "FCC disclaimer" FCC_disclaimer 2000,50 r0 top
Logo4 "WEEE logo" WEEE_Minimum 2000,350 r0 top
MH1 "MTG_NoPads" NPTH125mil 200,5800 r0 top
MH2 "MTG_NoPads" NPTH125mil 3800,5800 r0 top
R1 "RC0603JR-0747KL" 0603 1770,3950 r90 top value=47k
R2 "CRCW060351R0JNEA" 0603 2200,3950 r270 top value=51
R3 "CRCW0805100RJNEA" 0805_HV 3150,4000 r90 top value=100
R4 "CRCW080510K0JNEA" 0805_HV 3240,4000 r90 top value=10k
R5 "CRCW06031M00JNEA" 0603 2270,3950 r90 top value=1.0Meg
R6 "RC0603FR-074K87L" 0603 1820,2130 r0 top value=4.87k
R7 "RC0805JR-070RL" 0805_HV 2600,5800 r90 top value=0
R8 "RC0603FR-0749R9L" 0603 840,1760 r90 top value=49.9
R9 "RC0603FR-0749R9L" 0603 840,1635 r270 top value=49.9
R10 "CRCW08054K70JNEA" 0805_HV 2220,4900 r270 top value=4.7k
R11 "CRCW08054K70JNEA" 0805_HV 2130,4900 r270 top value=4.7k
R12 "RC0603FR-0749R9L" 0603 1000,1761.02 r90 top value=49.9
R13 "RC0603FR-0749R9L" 0603 1000,1635 r270 top value=49.9
R14 "CRCW06031M00JNEA" 0603 940,450 r90 top value=1.0Meg
R15 "RC0805JR-070RL" 0805_HV 2700,5800 r90 top value=0
R16 "RC0603JR-07330RL" 0603 900,310 r180 top value=330
R17 "CRCW080527R0JNEA" 0805_HV 1050,5400 r270 top value=27
R18 "CRCW080527R0JNEA" 0805_HV 1150,5400 r270 top value=27
R19 "CRCW080527R0JNEA" 0805_HV 1250,5400 r270 top value=27
R20 "CRCW080527R0JNEA" 0805_HV 1950,5100 r0 top value=27
R21 "CRCW080527R0JNEA" 0805_HV 1950,5000 r0 top value=27
R22 "CRCW080527R0JNEA" 0805_HV 1950,5200 r0 top value=27
R23 "RC0603JR-07330RL" 0603 900,230 r180 top value=330
R24 "RC0805JR-070RL" 0805_HV 800,5400 r270 top value=0
R25 "RC0805JR-070RL" 0805_HV 700,5400 r270 top value=0
R26 "CRCW06030000Z0EA" 0603 3100,2030 r180 top value=0
R27 "CRCW06030000Z0EA" 0603 3100,1970 r0 top value=0
R28 "CRCW06030000Z0EA" 0603 3100,1850 r180 top value=0
R29 "CRCW06030000Z0EA" 0603 3100,1910 r0 top value=0
R30 "CRCW0603100RJNEA" 0603 3100,2100 r0 top value=100
R31 "RC0603JR-0733KL" 0603 3000,190 r0 top value=33k
R32 "CRCW080510K0JNEA" 0805_HV 3200,640 r270 top value=10k
R33 "CRCW080510K0JNEA" 0805_HV 2750,445 r0 top value=10k
R34 "CRCW080527R0JNEA" 0805_HV 1850,5400 r270 top value=27
R35 "RC1608J103CS" 0603 1150,5200 r90 top value=10k
R36 "RC1608J103CS" 0603 1050,5200 r90 top value=10k
R37 "RC1608J103CS" 0603 950,5200 r90 top value=10k
R38 "CRCW080527R0JNEA" 0805_HV 1750,5400 r270 top value=27
R39 "RC0603FR-07100RL" 0603 2450,5800 r90 top value=100
R40 "CRCW080527R0JNEA" 0805_HV 1650,5400 r270 top value=27
R41 "CRCW080527R0JNEA" 0805_HV 1550,5400 r270 top value=27
R42 "CRCW08050000Z0EA" 0805_HV 1850,4500 r270 top value=0
R43 "CRCW08050000Z0EA" 0805_HV 1750,4500 r270 top value=0
SH-J7-1 "SNT-100-BK-G" SNT-100-BK-G 350,4700 r180 top value=1x2
SH-J7-2 "SNT-100-BK-G" SNT-100-BK-G 350,4600 r180 top value=1x2
SH-J7-3 "SNT-100-BK-G" SNT-100-BK-G 350,4500 r180 top value=1x2
SH-J7-4 "SNT-100-BK-G" SNT-100-BK-G 350,4400 r180 top value=1x2
SH-J7-5 "SNT-100-BK-G" SNT-100-BK-G 350,4300 r180 top value=1x2
SH-J7-6 "SNT-100-BK-G" SNT-100-BK-G 350,4200 r180 top value=1x2
SH-J7-7 "SNT-100-BK-G" SNT-100-BK-G 350,4100 r180 top value=1x2
SH-J7-8 "SNT-100-BK-G" SNT-100-BK-G 350,4000 r180 top value=1x2
SH-J7-9 "SNT-100-BK-G" SNT-100-BK-G 350,3900 r180 top value=1x2
SH-J7-10 "SNT-100-BK-G" SNT-100-BK-G 350,3800 r180 top value=1x2
SH-J7-11 "SNT-100-BK-G" SNT-100-BK-G 350,3700 r180 top value=1x2
SH-J7-12 "SNT-100-BK-G" SNT-100-BK-G 350,3600 r180 top value=1x2
SH-J7-13 "SNT-100-BK-G" SNT-100-BK-G 350,3500 r180 top value=1x2
SH-J7-14 "SNT-100-BK-G" SNT-100-BK-G 350,3400 r180 top value=1x2
SH-J7-15 "SNT-100-BK-G" SNT-100-BK-G 350,3300 r180 top value=1x2
SH-J7-16 "SNT-100-BK-G" SNT-100-BK-G 350,3200 r180 top value=1x2
SH-J7-17 "SNT-100-BK-G" SNT-100-BK-G 350,3100 r180 top value=1x2
SH-J7-18 "SNT-100-BK-G" SNT-100-BK-G 350,3000 r180 top value=1x2
SH-J7-19 "SNT-100-BK-G" SNT-100-BK-G 350,2900 r180 top value=1x2
SH-J7-20 "SNT-100-BK-G" SNT-100-BK-G 350,2800 r180 top value=1x2
SH-J7-21 "SNT-100-BK-G" SNT-100-BK-G 350,2700 r180 top value=1x2
SH-J7-22 "SNT-100-BK-G" SNT-100-BK-G 350,2600 r180 top value=1x2
SH-J7-23 "SNT-100-BK-G" SNT-100-BK-G 350,2500 r180 top value=1x2
SH-J7-24 "SNT-100-BK-G" SNT-100-BK-G 350,2400 r180 top value=1x2
SH-J7-25 "SNT-100-BK-G" SNT-100-BK-G 350,2300 r180 top value=1x2
SH-J7-26 "SNT-100-BK-G" SNT-100-BK-G 350,2200 r180 top value=1x2
SH-J7-27 "SNT-100-BK-G" SNT-100-BK-G 350,2100 r180 top value=1x2
SH-J7-28 "SNT-100-BK-G" SNT-100-BK-G 350,2000 r180 top value=1x2
SH-J7-29 "SNT-100-BK-G" SNT-100-BK-G 350,1900 r180 top value=1x2
SH-J7-30 "SNT-100-BK-G" SNT-100-BK-G 350,1800 r180 top value=1x2
SH-J7-31 "SNT-100-BK-G" SNT-100-BK-G 350,1700 r180 top value=1x2
SH-J7-32 "SNT-100-BK-G" SNT-100-BK-G 350,1600 r180 top value=1x2
SH-J7-33 "SNT-100-BK-G" SNT-100-BK-G 350,1500 r180 top value=1x2
SH-J7-34 "SNT-100-BK-G" SNT-100-BK-G 350,1400 r180 top value=1x2
SH-J7-35 "SNT-100-BK-G" SNT-100-BK-G 350,1300 r180 top value=1x2
SH-J7-36 "SNT-100-BK-G" SNT-100-BK-G 350,1200 r180 top value=1x2
SH-JP1 "SNT-100-BK-G" SNT-100-BK-G 150,5500 r180 top value=1x2
SH-JP2 "SNT-100-BK-G" SNT-100-BK-G 150,5100 r180 top value=1x2
SH-JP3 "SNT-100-BK-G" SNT-100-BK-G 150,5300 r180 top value=1x2
SH-JP4 "SNT-100-BK-G" SNT-100-BK-G 2600,1950 r90 top value=1x2
SH-JP5 "SNT-100-BK-G" SNT-100-BK-G 2800,1950 r90 top value=1x2
SH-JP6 "SNT-100-BK-G" SNT-100-BK-G 1650,500 r180 top value=1x2
SH-JP7 "SNT-100-BK-G" SNT-100-BK-G 1650,300 r180 top value=1x2
SH-JP8 "SNT-100-BK-G" SNT-100-BK-G 750,5000 r180 top value=1x2
SH-JP9 "SNT-100-BK-G" SNT-100-BK-G 1400,3750 r90 top value=1x2
SW1 "EVQ-11A04M" SW_EVQ11_04 2950,3950 r270 top
SW2 "EVQ-11A04M" SW_EVQ11_04 1950,3950 r270 top
SW3 "78H01T" SW_78H01T 3750,5000 r90 top
SW4 "78F01T" SW_78F01T 3250,5000 r90 top
SW5 "78F01T" SW_78F01T 2850,5000 r90 top
SW6 "78F01T" SW_78F01T 2450,5000 r90 top
SW7 "EVQ-11A04M" SW_EVQ11_04 2450,3950 r270 top
TP1 "5001" Keystone5001 300,4950 r90 top
TP2 "5001" Keystone5001 300,4850 r90 top
TP3 "5001" Keystone5001 3200,5300 r270 top
TP4 "5001" Keystone5001 3300,5300 r270 top
TP5 "5001" Keystone5001 2800,5300 r90 top
TP6 "5001" Keystone5001 2900,5300 r90 top
TP7 "5001" Keystone5001 3600,5300 r90 top
TP8 "5001" Keystone5001 3700,5300 r90 top
TP9 "5001" Keystone5001 3800,5300 r90 top
TP10 "5001" Keystone5001 3900,5300 r90 top
U1 "MSP432E411YTZAD" ZAD0212A 2200,2400 r270 top
U2 "IS42S16320F-7TL" TSOP-2_54 1100,3100 r0 top
U3 "TPS2051BDBVR" DBV0005A_N 3000,400 r180 top
U4 "TPD4S012DRYR" DRY0006A 3280,320 r90 top
U5 "TPS73533DRVR" DRV0006A 900,4800 r0 top
Y1 "603-25-261" NDK_NX3225GA 2425,1800 r90 top
Y2 "CMR200T-32.768KDZY-UT" CFM_CMR200T 2020,1700 r90 top
ZZ2 "These assemblies are ESD sensitive, ESD precautions shall be observed." AssemblyNote 205,6549.11 r0 top
ZZ3 "These assemblies must be clean and free from flux and all contaminants. Use of no clean flux is not acceptable." AssemblyNote 205,6460.56 r0 top
ZZ4 "These assemblies must comply with workmanship standards IPC-A-610 Class 2, unless otherwise specified." AssemblyNote 205,6372 r0 top
ZZ5 "Screws H3 and H4 should be screwed into standoffs H1 and H2, through the PCB" AssemblyNote 205,6290 r0 top
ZZ6 "Clip leads of SW1, SW2, and SW6 to withing 0.1\" of PCB after assembly" AssemblyNote 205,6205 r0 top

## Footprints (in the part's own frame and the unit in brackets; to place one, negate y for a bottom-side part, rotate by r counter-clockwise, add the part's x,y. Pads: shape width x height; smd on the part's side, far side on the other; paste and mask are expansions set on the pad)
0402 [mm] "0402 from SM-752 data"
  rect 0.8x0.6 smd: 1(-0.6,0) 2(0.6,0)
  silkscreen extent -1.22,-0.52 1.22,0.52, body extent -0.55,-0.3 0.55,0.3, height 0.6
0603 [mm] "0603 from SM-752 data"
  rect 1x0.95 smd: 1(-0.8,0) 2(0.8,0)
  silkscreen extent -1.52,-0.69 1.52,0.69, body extent -0.87,-0.47 0.87,0.47, height 1
0805_HV [mil] "0805 with 30mil clearance between pads"
  rect 50x63 smd: 1(-40,0) 2(40,0)
  silkscreen extent -74,-40 74,40, body extent -43,-29 43,29, height 57
AssemblyNote [mil] "Assembly Note"
Assman_AWHW-10G-0x02-T [mm] "Header, 2.54mm, 5x2, TH"
  rect 1.55x1.55 hole 1.02: 1(-1.27,5.08)
  round 1.55 hole 1.02: 2(1.27,5.08) 3(-1.27,2.54) 4(1.27,2.54) 5(-1.27,0) 6(1.27,0) 7(-1.27,-2.54) 8(1.27,-2.54) 9(-1.27,-5.08) 10(1.27,-5.08)
  silkscreen extent -4.9,-10.31 4.47,10.31, body extent -4.47,-10.31 4.47,10.31, height 9.15
BoosterPack_40pin_J1J3 [mm] "Receptacle, 2.54mm, 10x2, TH"
  rrect6% 1.55x1.55 hole 1.02: 1(1.27,11.43)
  round 1.55 hole 1.02: 2(1.27,8.89) 3(1.27,6.35) 4(1.27,3.81) 5(1.27,1.27) 6(1.27,-1.27) 7(1.27,-3.81) 8(1.27,-6.35) 9(1.27,-8.89) 10(1.27,-11.43) 21(-1.27,11.43) 22(-1.27,8.89) 23(-1.27,6.35) 24(-1.27,3.81) 25(-1.27,1.27) 26(-1.27,-1.27) 27(-1.27,-3.81) 28(-1.27,-6.35) 29(-1.27,-8.89) 30(-1.27,-11.43)
  silkscreen extent -7.62,-12.95 7.62,12.95, body extent -2.48,-12.95 2.48,12.95, height 8.51
BoosterPack_40pin_J2J4 [mm] "Receptacle, 2.54mm, 10x2, TH"
  round 1.55 hole 1.02: 11(-1.27,-11.43) 12(-1.27,-8.89) 13(-1.27,-6.35) 14(-1.27,-3.81) 15(-1.27,-1.27) 16(-1.27,1.27) 17(-1.27,3.81) 18(-1.27,6.35) 19(-1.27,8.89) 20(-1.27,11.43) 31(1.27,-11.43) 32(1.27,-8.89) 33(1.27,-6.35) 34(1.27,-3.81) 35(1.27,-1.27) 36(1.27,1.27) 37(1.27,3.81) 38(1.27,6.35) 39(1.27,8.89) 40(1.27,11.43)
  silkscreen extent -7.62,-12.95 2.48,12.95, body extent -2.48,-12.95 2.48,12.95, height 8.51
CE_Mark_5mm [mil] "Minimum text height for CE Mark"
  silkscreen extent -138,-98 138,98
CFM_CMR200T [mm] "SMD, 3-Leads, Dia 1.9mm"
  rect 2.5x1 smd: 1(3.375,1.25) 2(3.375,-1.25)
  rect 2.5x2.5 smd: 3(-4.375,0)
  silkscreen extent -2.8,-1 2.42,1, body extent -4.62,-1.42 4.38,1.42, height 2
CONN_5103309-5 [mm] "TE Connectivity"
  rect 1.65x1.65 hole 1.016 mask+0: 1(-11.43,-1.27)
  round 1.65 hole 1.016 mask+0: 2(-11.43,1.27) 3(-8.89,-1.27) 4(-8.89,1.27) 5(-6.35,-1.27) 6(-6.35,1.27) 7(-3.81,-1.27) 8(-3.81,1.27) 9(-1.27,-1.27) 10(-1.27,1.27) 11(1.27,-1.27) 12(1.27,1.27) 13(3.81,-1.27) 14(3.81,1.27) 15(6.35,-1.27) 16(6.35,1.27) 17(8.89,-1.27) 18(8.89,1.27) 19(11.43,-1.27) 20(11.43,1.27)
  silkscreen extent -16.51,-4.57 16.51,4.57, body extent -16.51,-4.57 16.51,4.57, height 9.87
DBV0005A_N [mm] "SOT23, 5-Leads, Body 2.9x1.6mm, Pitch 0.95mm, Lead Span 2.8mm, IPC Medium Density"
  rrect17% 1x0.6 smd: 1(-1.375,0.95) 2(-1.375,0) 3(-1.375,-0.95) 4(1.375,-0.95) 5(1.375,0.95)
  silkscreen extent -0.25,-1.55 0.25,1.55, body extent -1.42,-1.46 1.42,1.46, height 1.09
DRV0006A [mm] "SON, 6-Leads, Body 2x2mm, Pitch 0.65mm, Thermal Pad 1.6x1mm, TI Recommended"
  rrect33% 0.45x0.3 smd: 1(-0.975,0.65) 2(-0.975,0) 3(-0.975,-0.65) 4(0.975,-0.65) 5(0.975,0) 6(0.975,0.65)
  rrect14% 1x0.7 on Top Paste: 7(0,-0.45) 7(0,0.45)
  rrect10% 1x1.6 smd paste-0.5: 7(0,0)
  silkscreen extent -1.05,-1.2 1.05,1.2, body extent -1.05,-1.05 1.05,1.05, height 0.81
DRY0006A [mm] "PSON, 6-Leads, Body 1x1.45mm, Pitch 0.5mm, TI Recommended"
  rrect50% 0.35x0.2 smd: 1(-0.275,0.5)
  rrect50% 0.3x0.2 smd: 2(-0.3,0) 3(-0.3,-0.5) 4(0.3,-0.5) 5(0.3,0) 6(0.3,0.5)
  body extent -0.5,-0.72 0.5,0.73, height 0.58
FCC_disclaimer [mil]
Fiducial10-20 [mm]
  round 1 smd mask+0.5: 1(0,0)
  Top Layer keep-out circle w1.178: c0,0 r0.5
Hirose-ZX62D-AB-5P8 [mm] "SMD, 5-Leads, Pitch 0.65mm"
  rect 0.4x1.35 smd: 1(-1.3,4.125) 2(-0.65,4.125) 3(0,4.125) 4(0.65,4.125) 5(1.3,4.125)
  rect 1.8x1.9 smd: 6(-1.15,1.325) 7(1.15,1.325)
  oval 1.225x1.9 hole 0.825 slot 1.5 at 90 deg: 8(-4.088,1.325) 9(4.088,1.325)
  oval 1.05x1.25 hole 0.65 slot 0.85 at 90 deg: 10(-2.225,4.45) 11(2.225,4.45)
  Top Layer region: -4,0.387 -2.6,0.387 -2.6,2.287 -4,2.287
  Top Layer region: 2.6,0.387 4,0.387 4,2.288 2.6,2.288
  silkscreen extent -4.7,2.5 4.7,4.8, body extent -4.7,-1.3 4.7,4.45, height 2.81
Keystone5001 [mil] "For Keystone 500x miniature loop terminals"
  round 80 hole 40: 1(0,0)
  body extent -49,-49 49,49, height 182
Keystone_1902B [mil] "Hex Standoff, 4-40 threaded, nylon"
  round 1 on Mech4: 0(0,0)
  body extent -145,-126 145,126, height 375
NDK_NX3225GA [mm] "NDK"
  rect 1.2x1.4 smd: 1(-0.8,1.1) 2(-0.8,-1.1) 3(0.8,-1.1) 4(0.8,1.1)
  silkscreen extent -1.9,-0.1 1.4,2, body extent -1.3,-1.65 1.3,1.65, height 0.9
NPTH125mil [mil]
  round 120 hole 125 unplated mask+15: 1(0,0)
Pulse_J0011D21BNL [mm] "Connector, RJ-45 with integrated magnetics, 1x1, R/A, TH"
  rrect7% 1.4x1.4 hole 0.89: 1(-4.445,17.14)
  round 1.4 hole 0.89: 2(-3.175,19.68) 3(-1.905,17.14) 4(-0.635,19.68) 5(0.635,17.14) 6(1.905,19.68) 7(3.175,17.14) 8(4.445,19.68)
  round 1.55 hole 1.02: 9(-6.325,5.89) 10(-3.785,7.41) 11(3.785,5.89) 12(6.325,7.41)
  round 2.1 hole 1.6: 13(-7.875,13.84) 14(7.875,13.84)
  round 3.25 hole 3.25 unplated mask+0: MH1(-5.715,10.79) MH2(5.715,10.79)
  Top Layer keep-out region: -8.13,0 8.13,0 8.13,2.92 -8.13,2.92
  silkscreen extent -8.75,0.23 8.13,21.59, body extent -8.13,0 8.13,21.59, height 13.84
Samtec_FTSH-105-01-x-D-K [mm] "Header, 1.27 mm, 5x2, TH"
  rect 1.05x1.05 hole 0.71: 1(-0.635,2.54)
  round 1.05 hole 0.71: 2(0.635,2.54) 3(-0.635,1.27) 4(0.635,1.27) 5(-0.635,0) 6(0.635,0) 7(-0.635,-1.27) 8(0.635,-1.27) 9(-0.635,-2.54) 10(0.635,-2.54)
  silkscreen extent -2.54,-3.17 2.54,3.2, body extent -2.54,-3.17 2.54,3.1, height 5.73
Samtec_FTSH-110-01-x-DV-K [mm] "Header (Shrouded), 1.27mm, 10x2, SMT"
  rect 2.79x0.74 smd: 1(-2.035,5.715) 2(2.035,5.715) 3(-2.035,4.445) 4(2.035,4.445) 5(-2.035,3.175) 6(2.035,3.175) 7(-2.035,1.905) 8(2.035,1.905) 9(-2.035,0.635) 10(2.035,0.635) 11(-2.035,-0.635) 12(2.035,-0.635) 13(-2.035,-1.905) 14(2.035,-1.905) 15(-2.035,-3.175) 16(2.035,-3.175) 17(-2.035,-4.445) 18(2.035,-4.445) 19(-2.035,-5.715) 20(2.035,-5.715)
  silkscreen extent -1.71,-6.35 1.71,6.7, body extent -2.92,-6.35 2.92,6.35, height 6.12
SAMTEC_HMTSW-102-07-G-S-240 [mm] "Header, 2.54mm, 2x1, TH"
  rect 1.55x1.55 hole 1.02: 1(-1.27,0)
  round 1.55 hole 1.02: 2(1.27,0)
  silkscreen extent -2.54,-1.24 2.54,1.24, body extent -2.54,-1.27 2.54,1.27, height 8.64
Samtec_TSW-104-07-T-S [mm] "Header, 2.54mm, 4x1, TH"
  rrect50% 1.55x1.55 hole 1.02: 1(-3.81,0)
  round 1.55 hole 1.02: 2(-1.27,0) 3(1.27,0) 4(3.81,0)
  body extent -5.21,-1.27 5.08,1.27, height 8.38
Samtec_TSW-136-07-x-D [mm] "Header, 2.54mm, 36x2, TH"
  rrect50% 1.53x1.53 hole 1.02: 1(-1.27,44.45)
  round 1.53 hole 1.02: 2(1.27,44.45) 3(-1.27,41.91) 4(1.27,41.91) 5(-1.27,39.37) 6(1.27,39.37) 7(-1.27,36.83) 8(1.27,36.83) 9(-1.27,34.29) 10(1.27,34.29) 11(-1.27,31.75) 12(1.27,31.75) 13(-1.27,29.21) 14(1.27,29.21) 15(-1.27,26.67) 16(1.27,26.67) 17(-1.27,24.13) 18(1.27,24.13) 19(-1.27,21.59) 20(1.27,21.59) 21(-1.27,19.05) 22(1.27,19.05) 23(-1.27,16.51) 24(1.27,16.51) 25(-1.27,13.97) 26(1.27,13.97) 27(-1.27,11.43) 28(1.27,11.43) 29(-1.27,8.89) 30(1.27,8.89) 31(-1.27,6.35) 32(1.27,6.35) 33(-1.27,3.81) 34(1.27,3.81) 35(-1.27,1.27) 36(1.27,1.27) 37(-1.27,-1.27) 38(1.27,-1.27) 39(-1.27,-3.81) 40(1.27,-3.81) 41(-1.27,-6.35) 42(1.27,-6.35) 43(-1.27,-8.89) 44(1.27,-8.89) 45(-1.27,-11.43) 46(1.27,-11.43) 47(-1.27,-13.97) 48(1.27,-13.97) 49(-1.27,-16.51) 50(1.27,-16.51) 51(-1.27,-19.05) 52(1.27,-19.05) 53(-1.27,-21.59) 54(1.27,-21.59) 55(-1.27,-24.13) 56(1.27,-24.13) 57(-1.27,-26.67) 58(1.27,-26.67) 59(-1.27,-29.21) 60(1.27,-29.21) 61(-1.27,-31.75) 62(1.27,-31.75) 63(-1.27,-34.29) 64(1.27,-34.29) 65(-1.27,-36.83) 66(1.27,-36.83) 67(-1.27,-39.37) 68(1.27,-39.37) 69(-1.27,-41.91) 70(1.27,-41.91) 71(-1.27,-44.45) 72(1.27,-44.45)
  body extent -2.54,-45.72 2.54,45.72, height 8.38
SNT-100-BK-G [mil] "Samtec STEP model"
  round 1 on Mech3: 0(0,0)
  body extent -100,-50 100,50, height 344
SOIC-8 [mm] "duplicate of SO-8.  SOIC, 8-Leads, Body 5.0x4.0mm (max), Pitch 1.27mm, IPC Medium Density"
  rrect17% 1.45x0.6 smd: 1(-2.725,1.905) 2(-2.725,0.635) 3(-2.725,-0.635) 4(-2.725,-1.905) 5(2.725,-1.905) 6(2.725,-0.635) 7(2.725,0.635) 8(2.725,1.905)
  silkscreen extent -3.5,-2.5 0.9,2.5, body extent -3,-2.45 3,2.45, height 1.63
SW_78F01T [mm] "TH, 4-Leads, Body 9.65x7.12mm, Pitch 2.54mm"
  rect 1.35x1.35 hole 0.85: 1(-3.81,1.27)
  round 1.35 hole 0.85: 2(3.81,1.27) 3(-3.81,-1.27) 4(3.81,-1.27)
  silkscreen extent -5.3,-3.69 4.95,3.69, body extent -4.95,-3.69 4.95,3.69, height 8.05
SW_78H01T [mm] "TH, 8-Leads, Body 9.65x12.2mm, Pitch 2.54mm"
  rect 1.35x1.35 hole 0.85: 1(-3.81,3.81)
  round 1.35 hole 0.85: 2(3.81,3.81) 3(-3.81,1.27) 4(3.81,1.27) 5(-3.81,-1.27) 6(3.81,-1.27) 7(-3.81,-3.81) 8(3.81,-3.81)
  silkscreen extent -5.3,-6.23 4.95,6.23, body extent -4.95,-6.23 4.95,6.23, height 8.05
SW_EVQ11_04 [mm] "TH, 2-Leads, Body 6x6mm"
  round 1.5 hole 1: 1(-2.5,0) 2(2.5,0)
  silkscreen extent -3,-3 3,3, body extent -3,-3 3,3, height 4.3
TI_Stacked_Overlay_Small [mil]
  silkscreen extent -418,-98 418,98
TSOP-2_54 [mm] "TSOP, 54-Leads, Body 22.22x10.16mm, Pitch 0.8mm"
  rrect18% 1.25x0.55 smd: 1(-5.775,10.4) 2(-5.775,9.6) 3(-5.775,8.8) 4(-5.775,8) 5(-5.775,7.2) 6(-5.775,6.4) 7(-5.775,5.6) 8(-5.775,4.8) 9(-5.775,4) 10(-5.775,3.2) 11(-5.775,2.4) 12(-5.775,1.6) 13(-5.775,0.8) 14(-5.775,0) 15(-5.775,-0.8) 16(-5.775,-1.6) 17(-5.775,-2.4) 18(-5.775,-3.2) 19(-5.775,-4) 20(-5.775,-4.8) 21(-5.775,-5.6) 22(-5.775,-6.4) 23(-5.775,-7.2) 24(-5.775,-8) 25(-5.775,-8.8) 26(-5.775,-9.6) 27(-5.775,-10.4) 28(5.775,-10.4) 29(5.775,-9.6) 30(5.775,-8.8) 31(5.775,-8) 32(5.775,-7.2) 33(5.775,-6.4) 34(5.775,-5.6) 35(5.775,-4.8) 36(5.775,-4) 37(5.775,-3.2) 38(5.775,-2.4) 39(5.775,-1.6) 40(5.775,-0.8) 41(5.775,0) 42(5.775,0.8) 43(5.775,1.6) 44(5.775,2.4) 45(5.775,3.2) 46(5.775,4) 47(5.775,4.8) 48(5.775,5.6) 49(5.775,6.4) 50(5.775,7.2) 51(5.775,8) 52(5.775,8.8) 53(5.775,9.6) 54(5.775,10.4)
  silkscreen extent -5.15,-11.2 5.15,11.5, body extent -5.15,-11.2 5.15,11.2, height 1.2
TSW-107-XX-XXX-S [mm] "2.54mm pitch, 7 pin, terminal strip; straight, single row"
  rrect6% 1.65x1.65 hole 1: 1(-7.62,-0.025)
  round 1.65 hole 1: 2(-5.08,0) 3(-2.54,0) 4(0,0) 5(2.54,0) 6(5.08,0) 7(7.62,0)
  silkscreen extent -8.92,-1.25 8.93,1.25, body extent -8.89,-1.27 8.89,1.27, height 8.38
TSW-120-07-G-D [mm] "Samtec 100mil, 2x20, 230 mil above insulator"
  rrect6% 1.65x1.65 hole 1.016: 1(-24.13,-1.27)
  round 1.65 hole 1.016: 2(-24.13,1.27) 3(-21.59,-1.27) 4(-21.59,1.27) 5(-19.05,-1.27) 6(-19.05,1.27) 7(-16.51,-1.27) 8(-16.51,1.27) 9(-13.97,-1.27) 10(-13.97,1.27) 11(-11.43,-1.27) 12(-11.43,1.27) 13(-8.89,-1.27) 14(-8.89,1.27) 15(-6.35,-1.27) 16(-6.35,1.27) 17(-3.81,-1.27) 18(-3.81,1.27) 19(-1.27,-1.27) 20(-1.27,1.27) 21(1.27,-1.27) 22(1.27,1.27) 23(3.81,-1.27) 24(3.81,1.27) 25(6.35,-1.27) 26(6.35,1.27) 27(8.89,-1.27) 28(8.89,1.27) 29(11.43,-1.27) 30(11.43,1.27) 31(13.97,-1.27) 32(13.97,1.27) 33(16.51,-1.27) 34(16.51,1.27) 35(19.05,-1.27) 36(19.05,1.27) 37(21.59,-1.27) 38(21.59,1.27) 39(24.13,-1.27) 40(24.13,1.27)
  silkscreen extent -25.4,-2.54 25.4,2.54, body extent -25.4,-2.54 25.4,2.54, height 8.38
WEEE_Minimum [mil] "WEEElie bin"
  silkscreen extent -95,-172 99,104
ZAD0212A [mm] "BGA, 212-Balls, Body 10x10mm, Pitch 0.5mm"
  round 0.25 smd: A1(-4.5,4.5) A2(-4,4.5) A4(-3,4.5) A5(-2.5,4.5) A7(-1.5,4.5) A8(-1,4.5) A10(0,4.5) A11(0.5,4.5) A13(1.5,4.5) A14(2,4.5) A16(3,4.5) A17(3.5,4.5) A18(4,4.5) A19(4.5,4.5) B1(-4.5,4) B2(-4,4) B3(-3.5,4) B4(-3,4) B5(-2.5,4) B6(-2,4) B7(-1.5,4) B8(-1,4) B9(-0.5,4) B10(0,4) B11(0.5,4) B12(1,4) B13(1.5,4) B14(2,4) B15(2.5,4) B16(3,4) B17(3.5,4) B18(4,4) B19(4.5,4) C1(-4.5,3.5) C2(-4,3.5) C5(-2.5,3.5) C6(-2,3.5) C8(-1,3.5) C10(0,3.5) C12(1,3.5) C14(2,3.5) C15(2.5,3.5) C18(4,3.5) D1(-4.5,3) D2(-4,3) D6(-2,3) D7(-1.5,3) D8(-1,3) D12(1,3) D13(1.5,3) D14(2,3) D18(4,3) D19(4.5,3) E2(-4,2.5) E3(-3.5,2.5) E7(-1.5,2.5) E10(0,2.5) E13(1.5,2.5) E17(3.5,2.5) E18(4,2.5) E19(4.5,2.5) F1(-4.5,2) F2(-4,2) F3(-3.5,2) F4(-3,2) F10(0,2) F16(3,2) F17(3.5,2) F18(4,2) G1(-4.5,1.5) G2(-4,1.5) G4(-3,1.5) G5(-2.5,1.5) G10(0,1.5) G15(2.5,1.5) G16(3,1.5) G18(4,1.5) G19(4.5,1.5) H2(-4,1) H3(-3.5,1) H4(-3,1) H9(-0.5,1) H10(0,1) H11(0.5,1) H12(1,1) H16(3,1) H17(3.5,1) H18(4,1) H19(4.5,1) J1(-4.5,0.5) J2(-4,0.5) J8(-1,0.5) J9(-0.5,0.5) J10(0,0.5) J11(0.5,0.5) J12(1,0.5) J18(4,0.5) K1(-4.5,0) K2(-4,0) K3(-3.5,0) K5(-2.5,0) K6(-2,0) K7(-1.5,0) K8(-1,0) K9(-0.5,0) K10(0,0) K11(0.5,0) K12(1,0) K13(1.5,0) K14(2,0) K15(2.5,0) K17(3.5,0) K18(4,0) K19(4.5,0) L2(-4,-0.5) L8(-1,-0.5) L9(-0.5,-0.5) L10(0,-0.5) L11(0.5,-0.5) L12(1,-0.5) L18(4,-0.5) L19(4.5,-0.5) M1(-4.5,-1) M2(-4,-1) M3(-3.5,-1) M4(-3,-1) M8(-1,-1) M9(-0.5,-1) M10(0,-1) M11(0.5,-1) M12(1,-1) M16(3,-1) M17(3.5,-1) M18(4,-1) N1(-4.5,-1.5) N2(-4,-1.5) N4(-3,-1.5) N5(-2.5,-1.5) N10(0,-1.5) N15(2.5,-1.5) N16(3,-1.5) N18(4,-1.5) N19(4.5,-1.5) P2(-4,-2) P3(-3.5,-2) P4(-3,-2) P10(0,-2) P16(3,-2) P17(3.5,-2) P18(4,-2) P19(4.5,-2) R1(-4.5,-2.5) R2(-4,-2.5) R3(-3.5,-2.5) R7(-1.5,-2.5) R10(0,-2.5) R13(1.5,-2.5) R17(3.5,-2.5) R18(4,-2.5) T1(-4.5,-3) T2(-4,-3) T6(-2,-3) T7(-1.5,-3) T8(-1,-3) T12(1,-3) T13(1.5,-3) T14(2,-3) T18(4,-3) T19(4.5,-3) U2(-4,-3.5) U5(-2.5,-3.5) U6(-2,-3.5) U8(-1,-3.5) U10(0,-3.5) U12(1,-3.5) U14(2,-3.5) U15(2.5,-3.5) U18(4,-3.5) U19(4.5,-3.5) V1(-4.5,-4) V2(-4,-4) V3(-3.5,-4) V4(-3,-4) V5(-2.5,-4) V6(-2,-4) V7(-1.5,-4) V8(-1,-4) V9(-0.5,-4) V10(0,-4) V11(0.5,-4) V12(1,-4) V13(1.5,-4) V14(2,-4) V15(2.5,-4) V16(3,-4) V17(3.5,-4) V18(4,-4) V19(4.5,-4) W1(-4.5,-4.5) W2(-4,-4.5) W3(-3.5,-4.5) W4(-3,-4.5) W6(-2,-4.5) W7(-1.5,-4.5) W9(-0.5,-4.5) W10(0,-4.5) W12(1,-4.5) W13(1.5,-4.5) W15(2.5,-4.5) W16(3,-4.5) W18(4,-4.5) W19(4.5,-4.5)
  silkscreen extent -5.77,-5 5,5, body extent -5,-5 5,5, height 1.1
